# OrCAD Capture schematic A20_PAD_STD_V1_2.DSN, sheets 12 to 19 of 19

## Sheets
12 P12: NAND&eMMC: size A3; note: NAND&eMMC
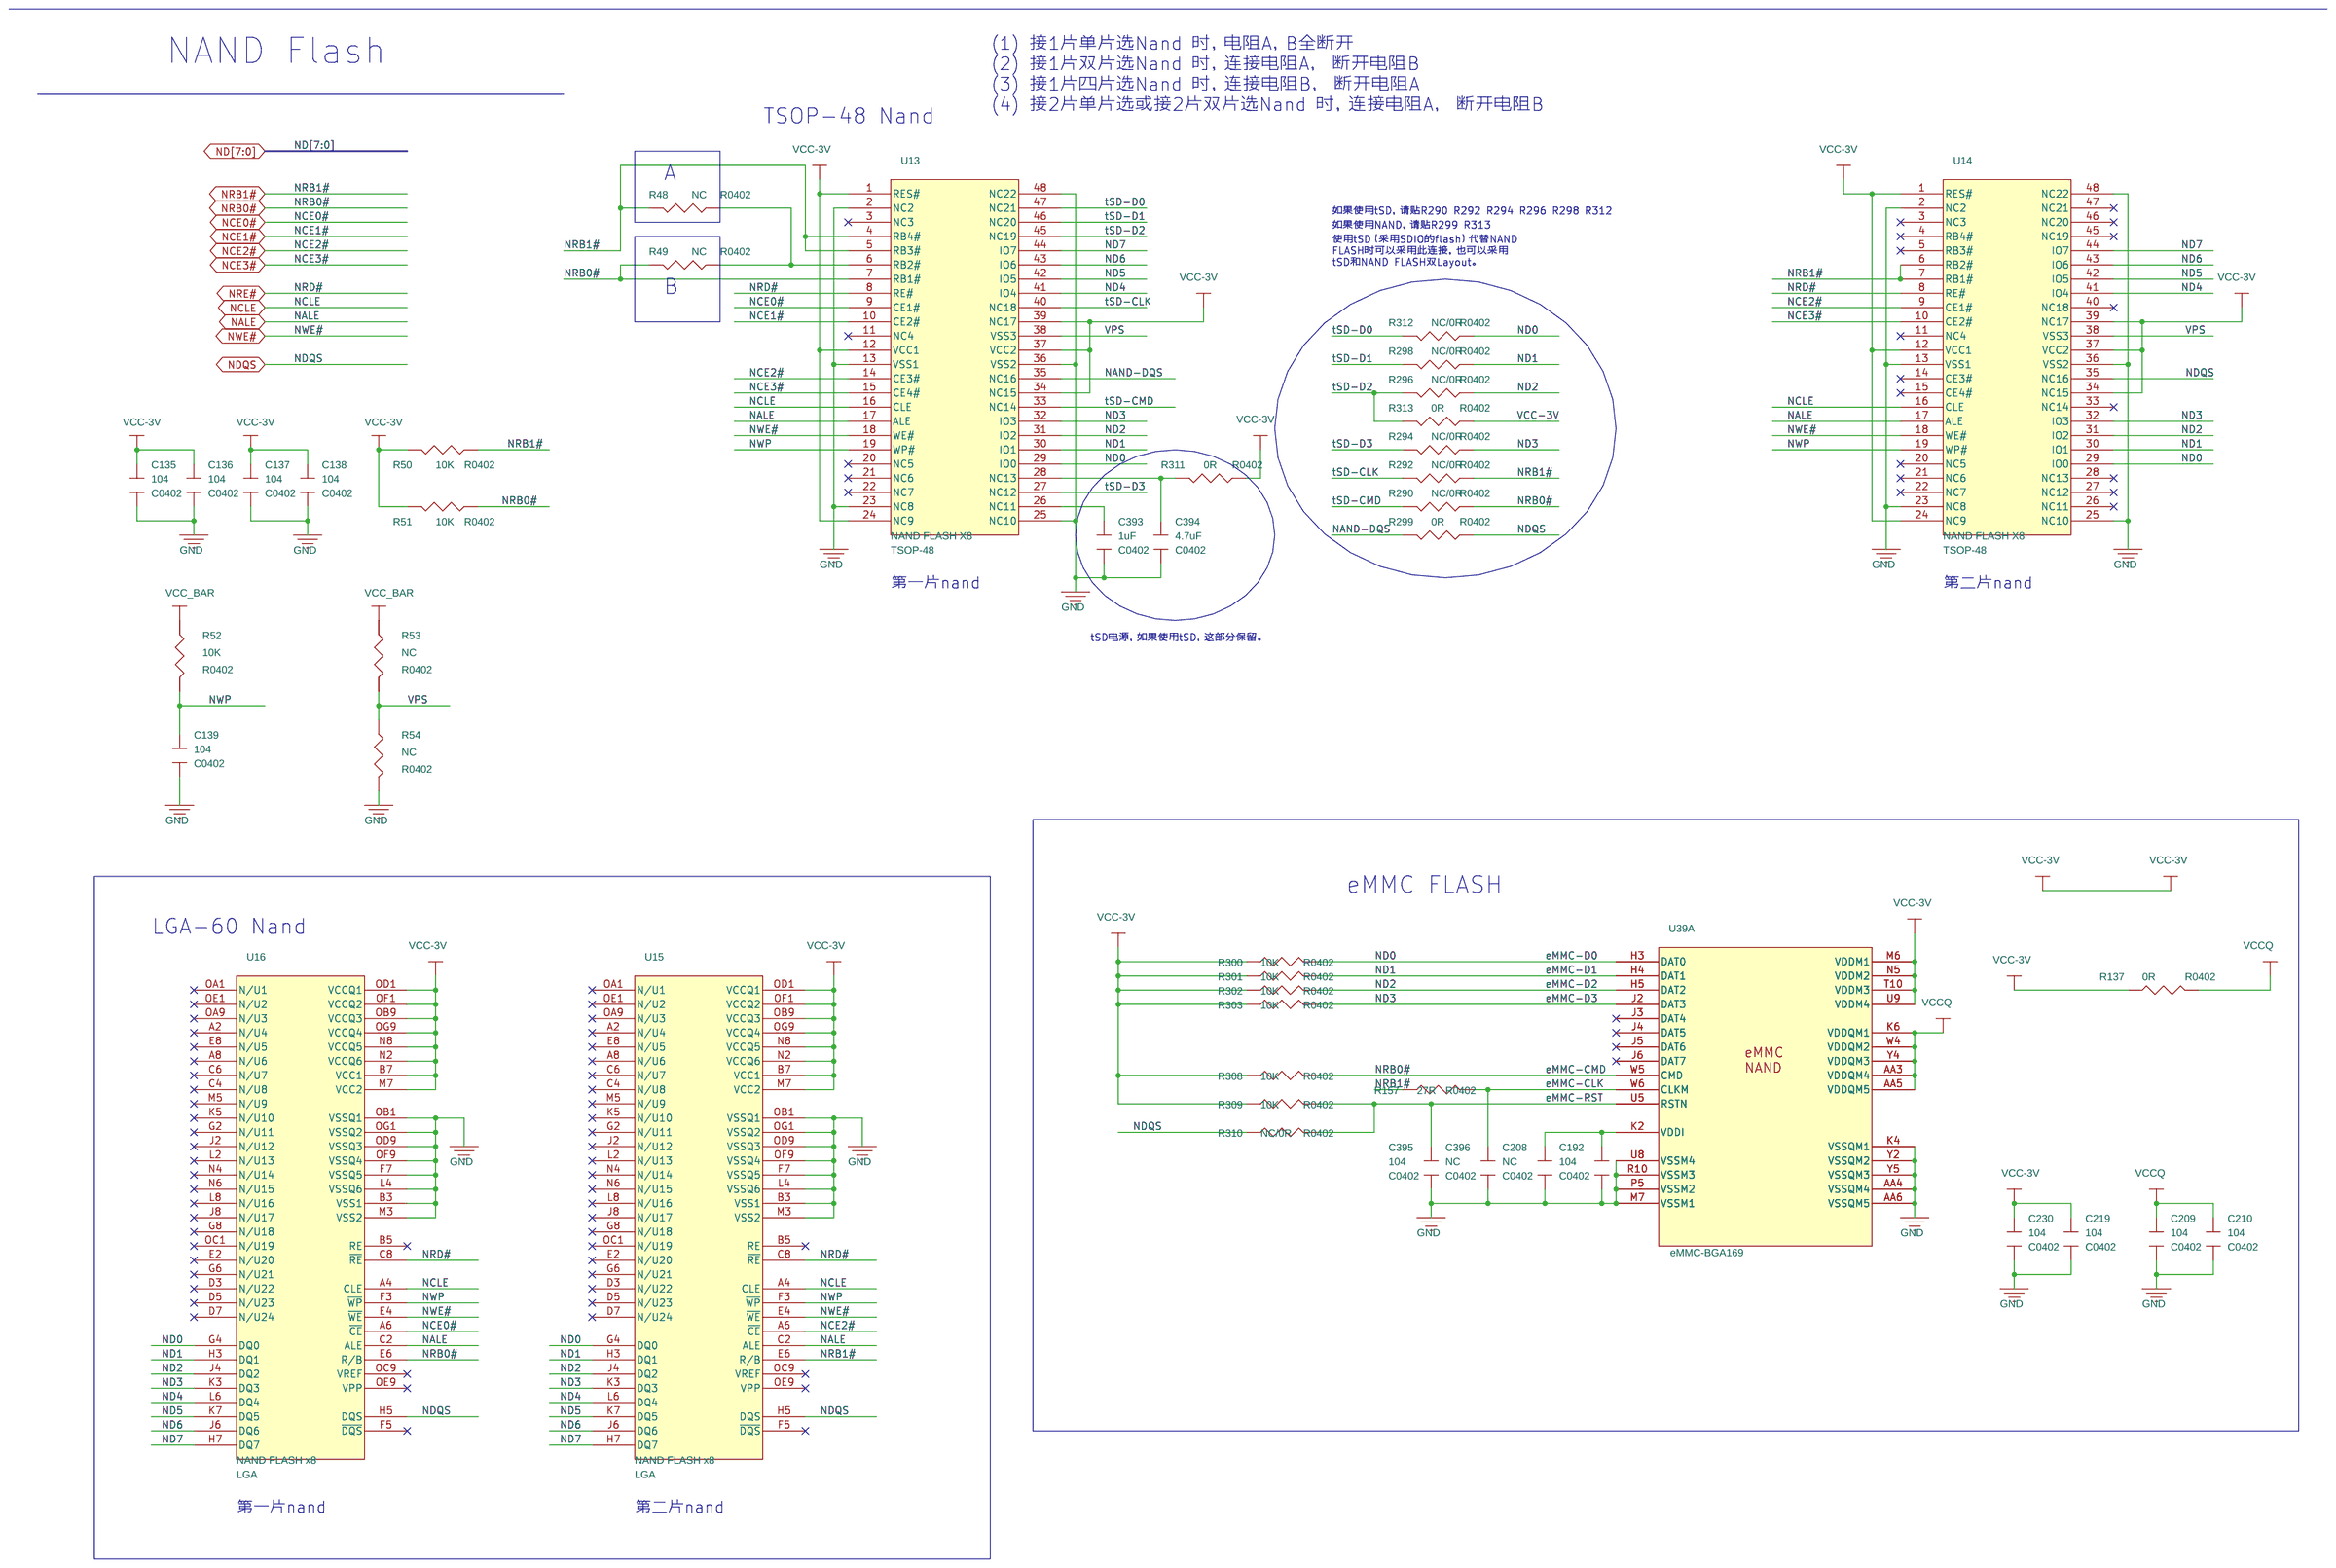
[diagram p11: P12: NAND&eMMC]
13 P15: CARD-DEBUG-GS: size A3; note: CARD-DEBUG-GS
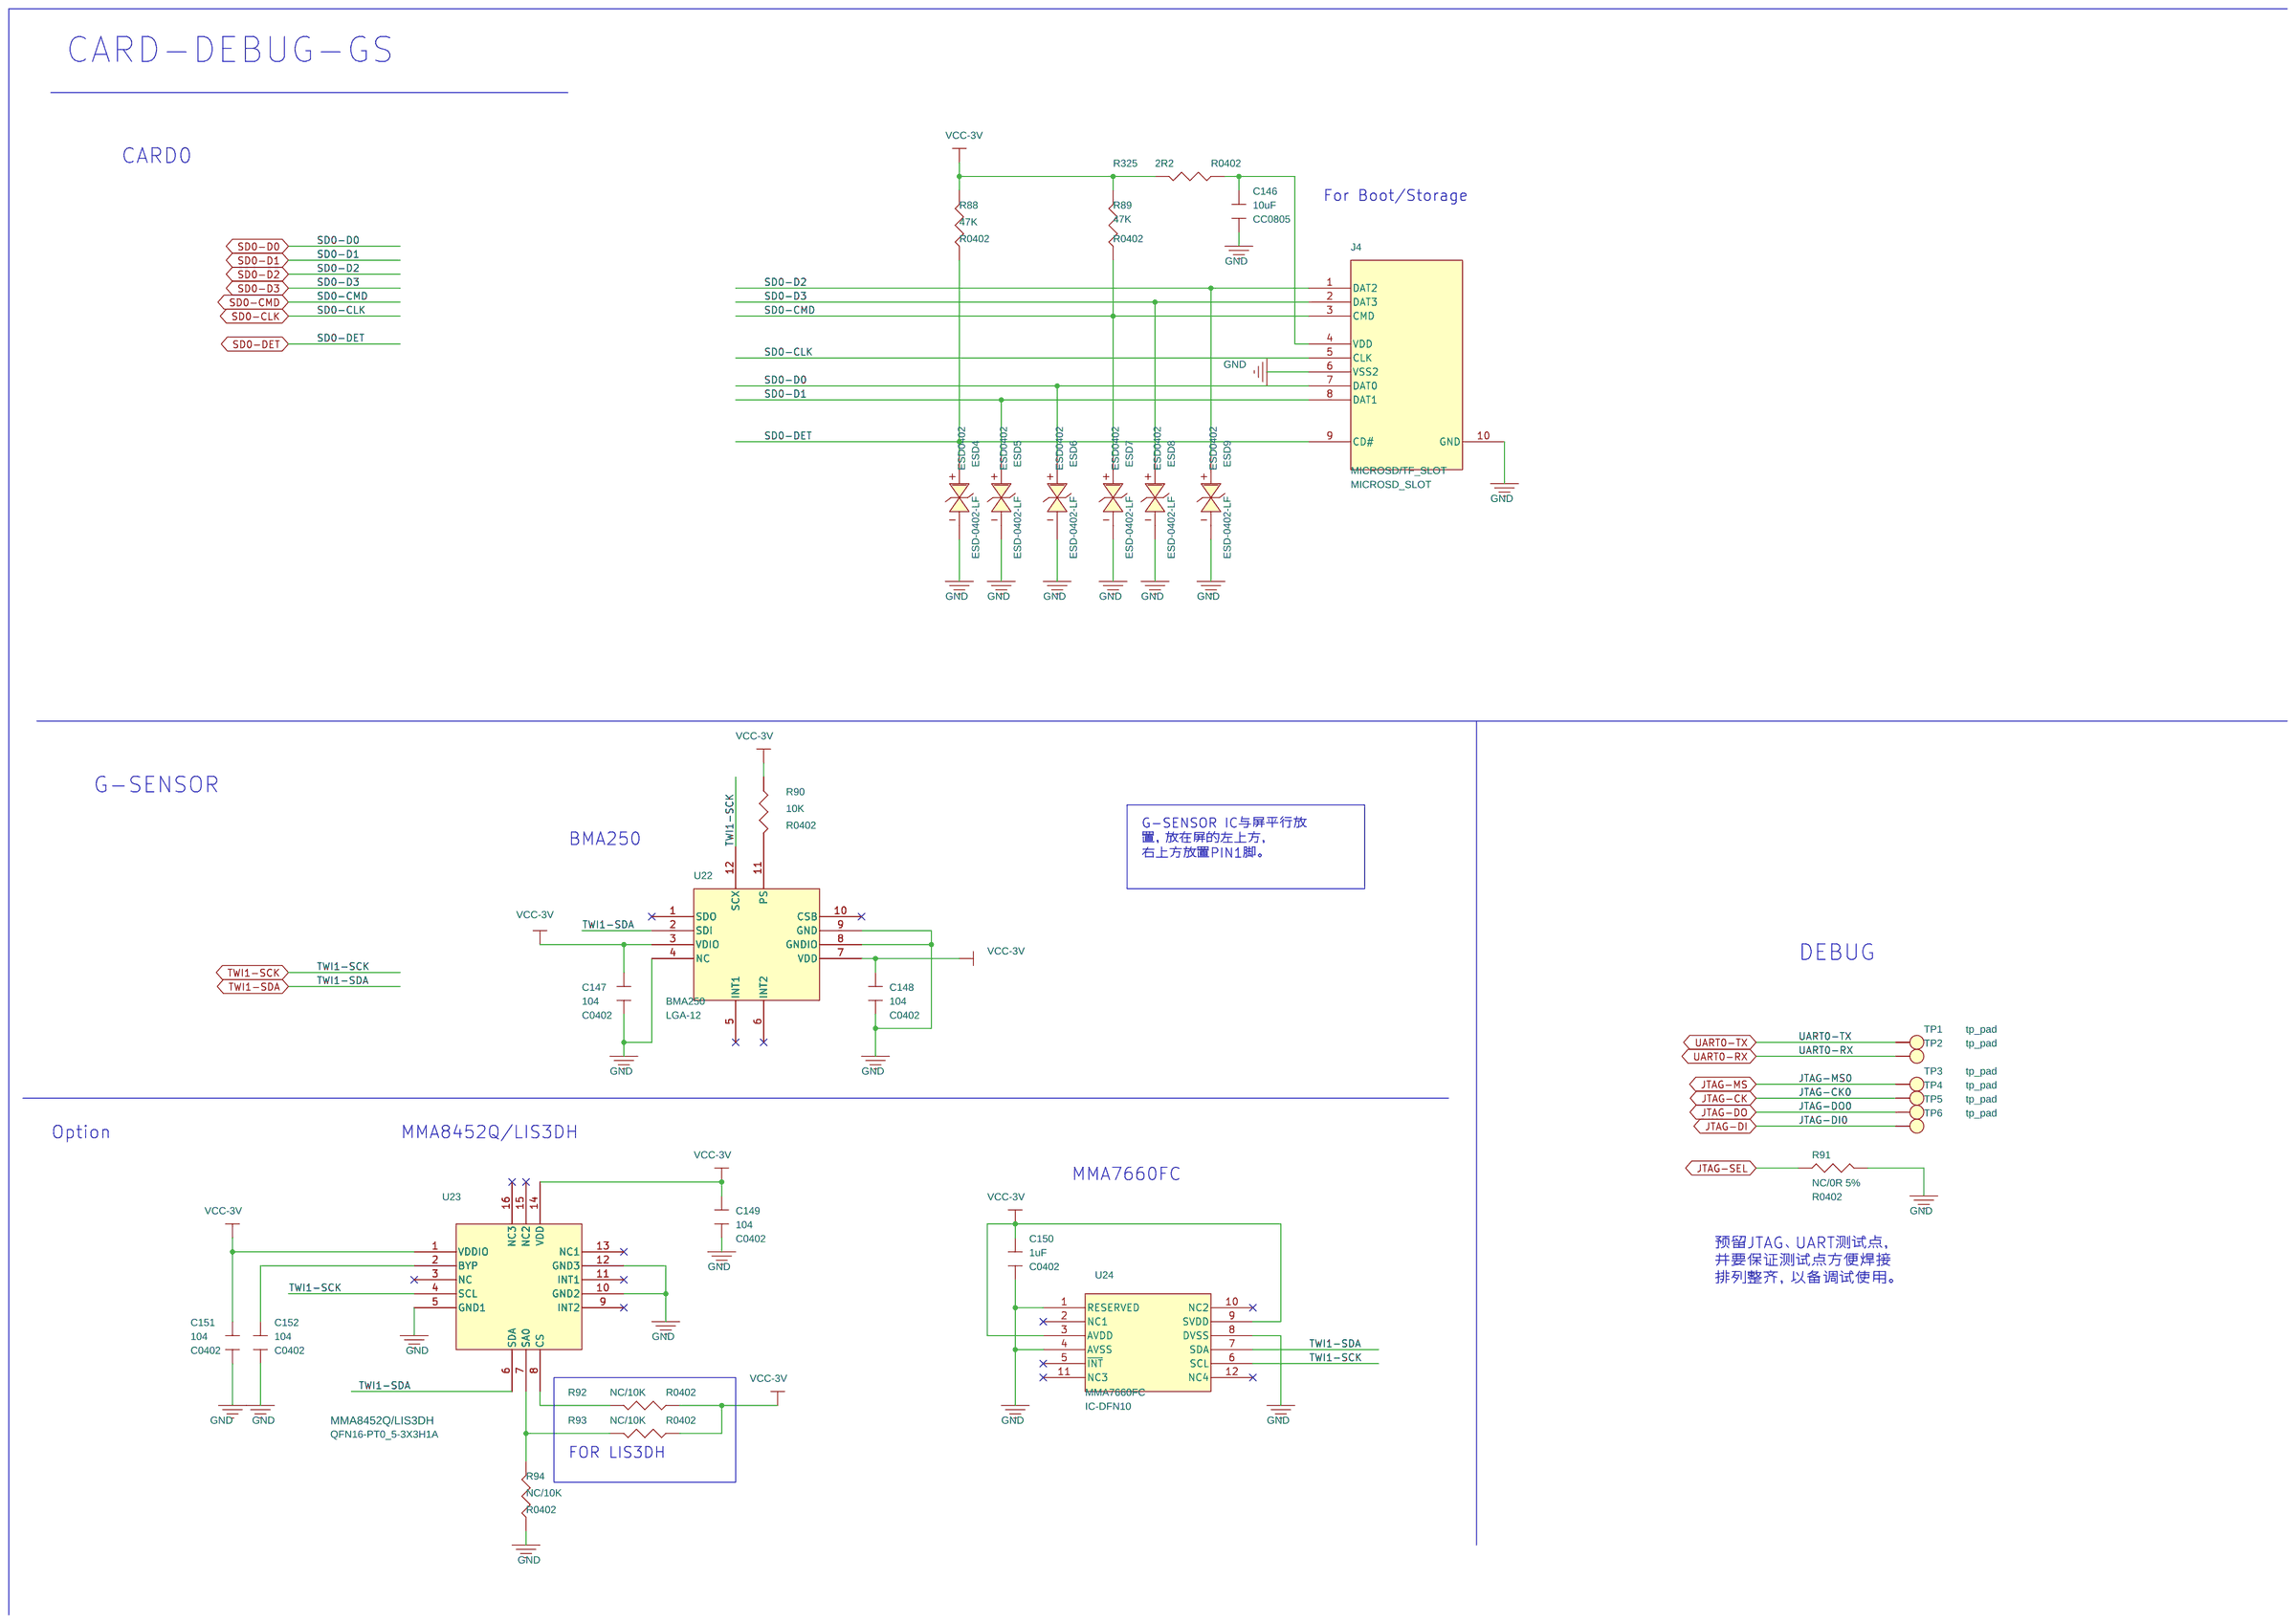
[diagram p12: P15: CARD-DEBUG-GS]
14 P09: BESIDE CPU: size A3; note: BESIDE CPU
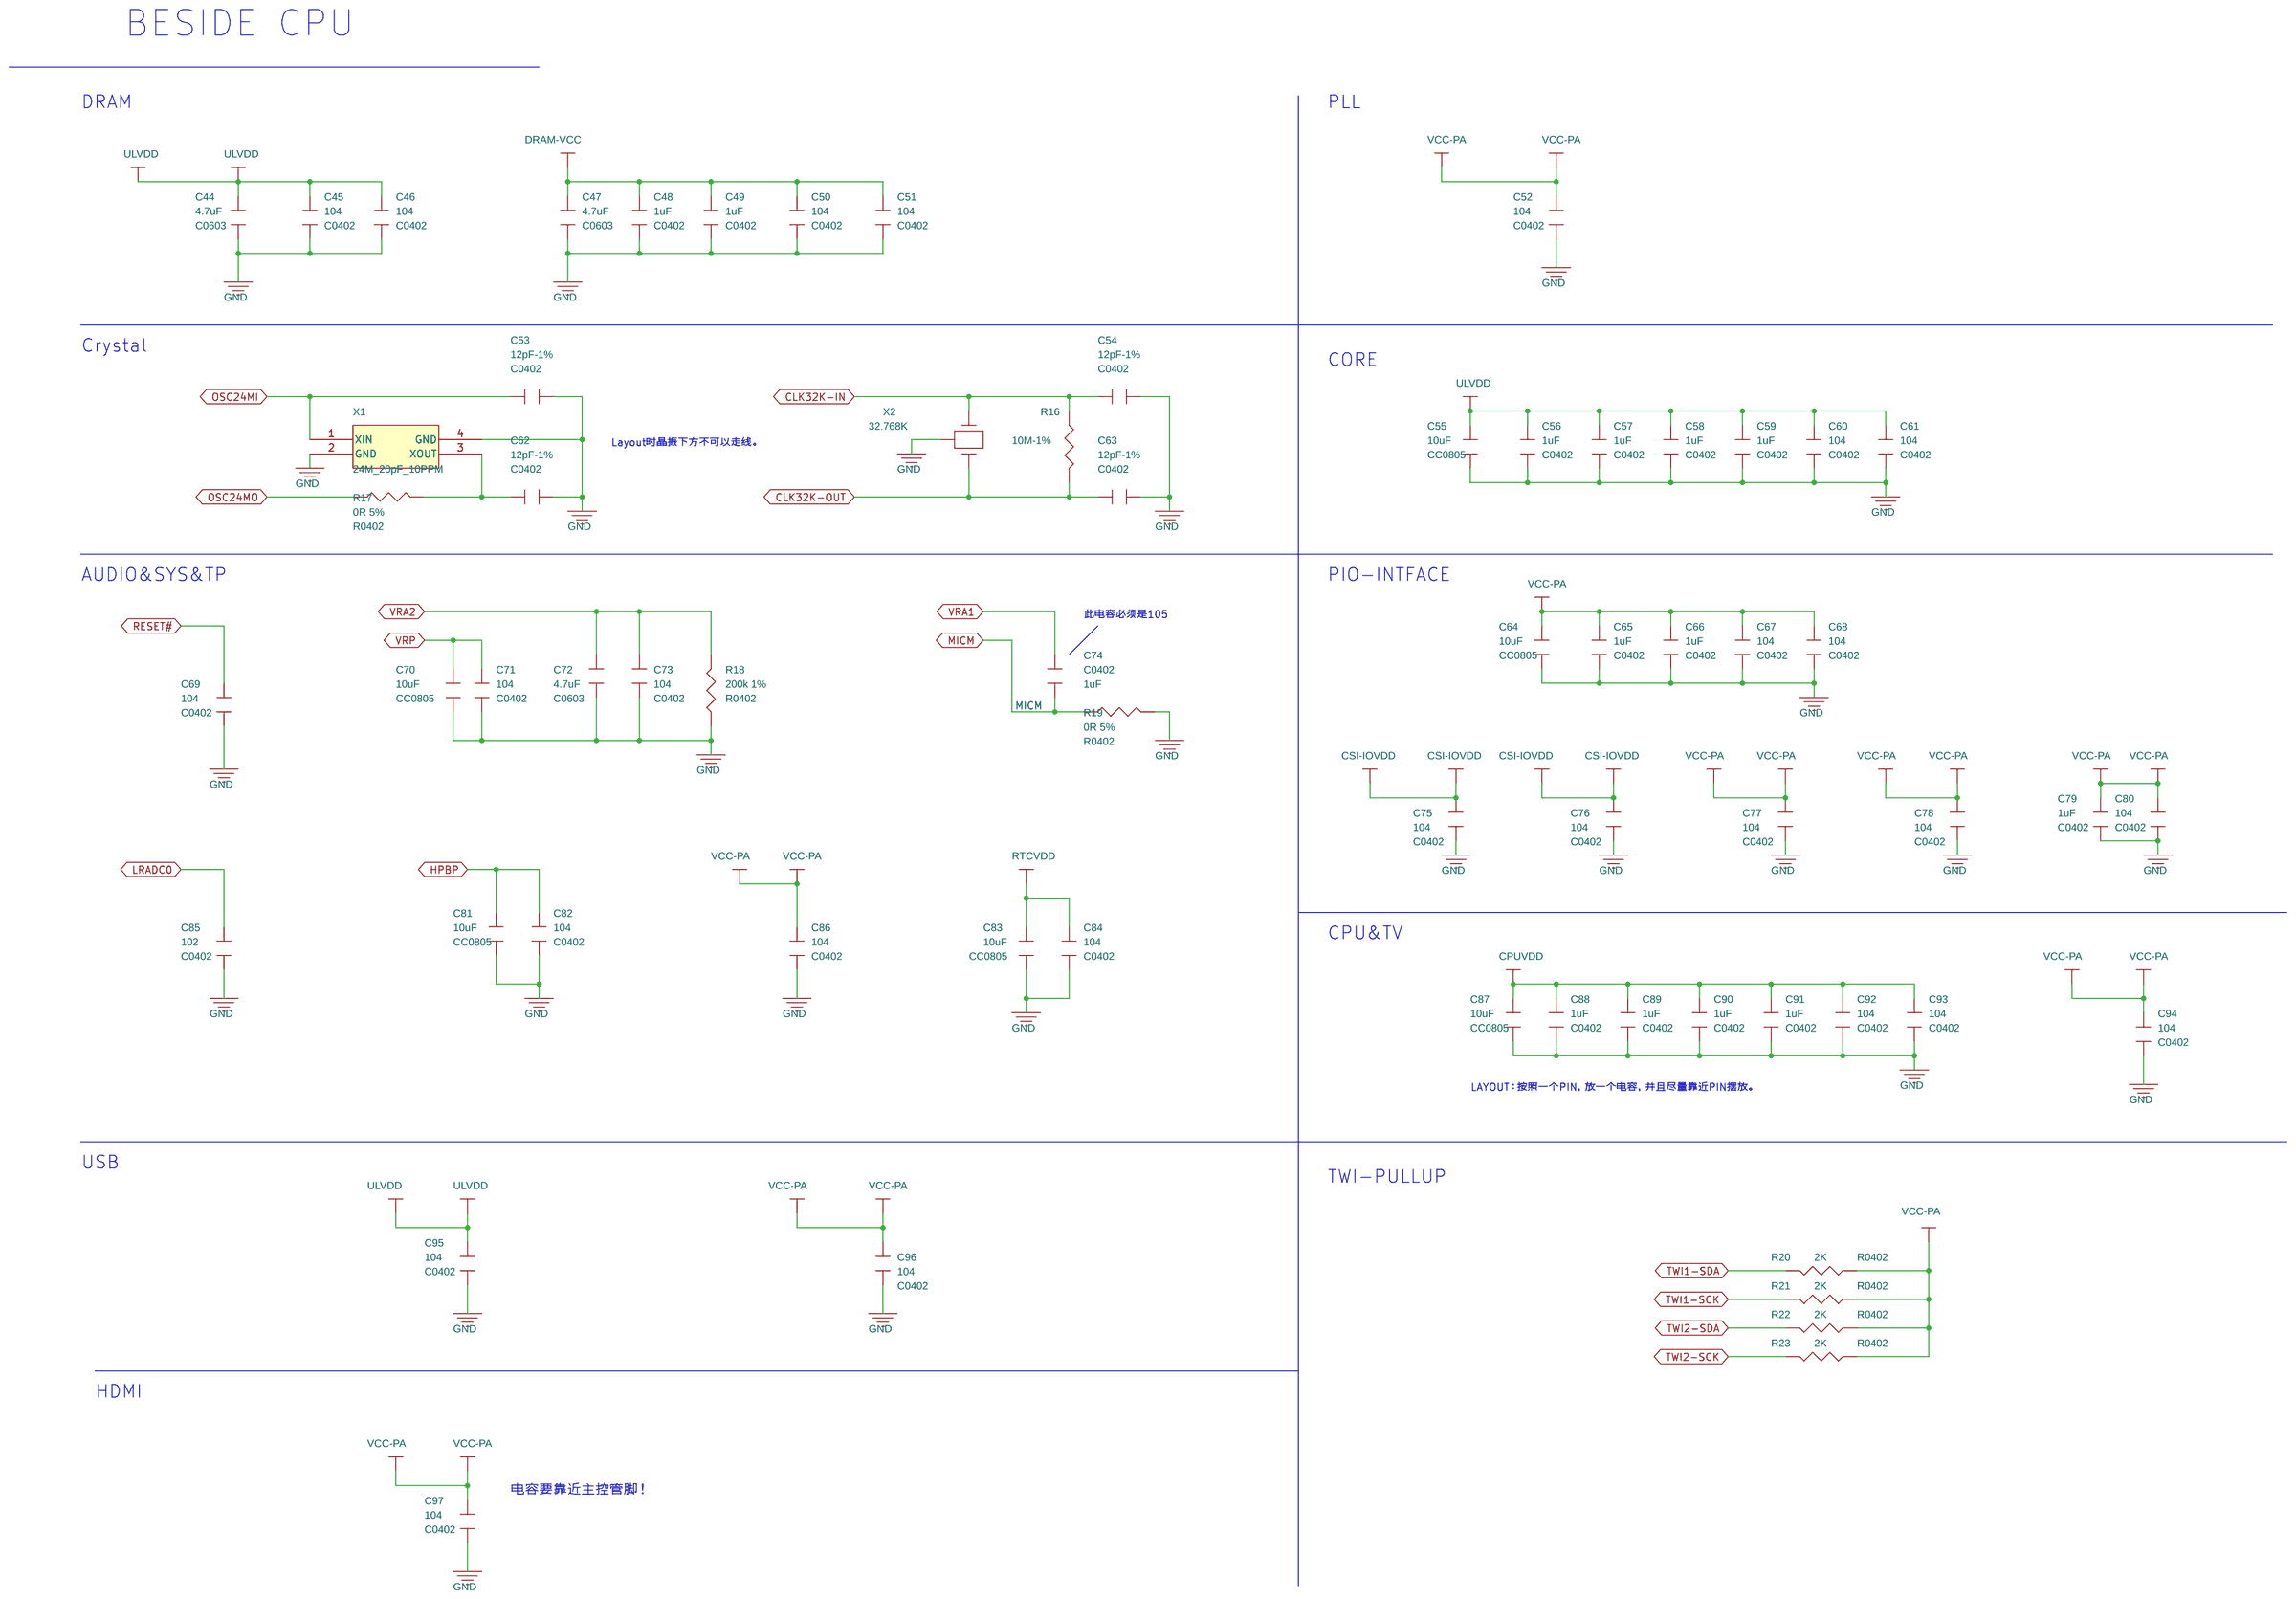
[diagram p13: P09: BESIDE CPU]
15 P19: HP-MIC-SPK: size A3; note: HP-MIC-SPK
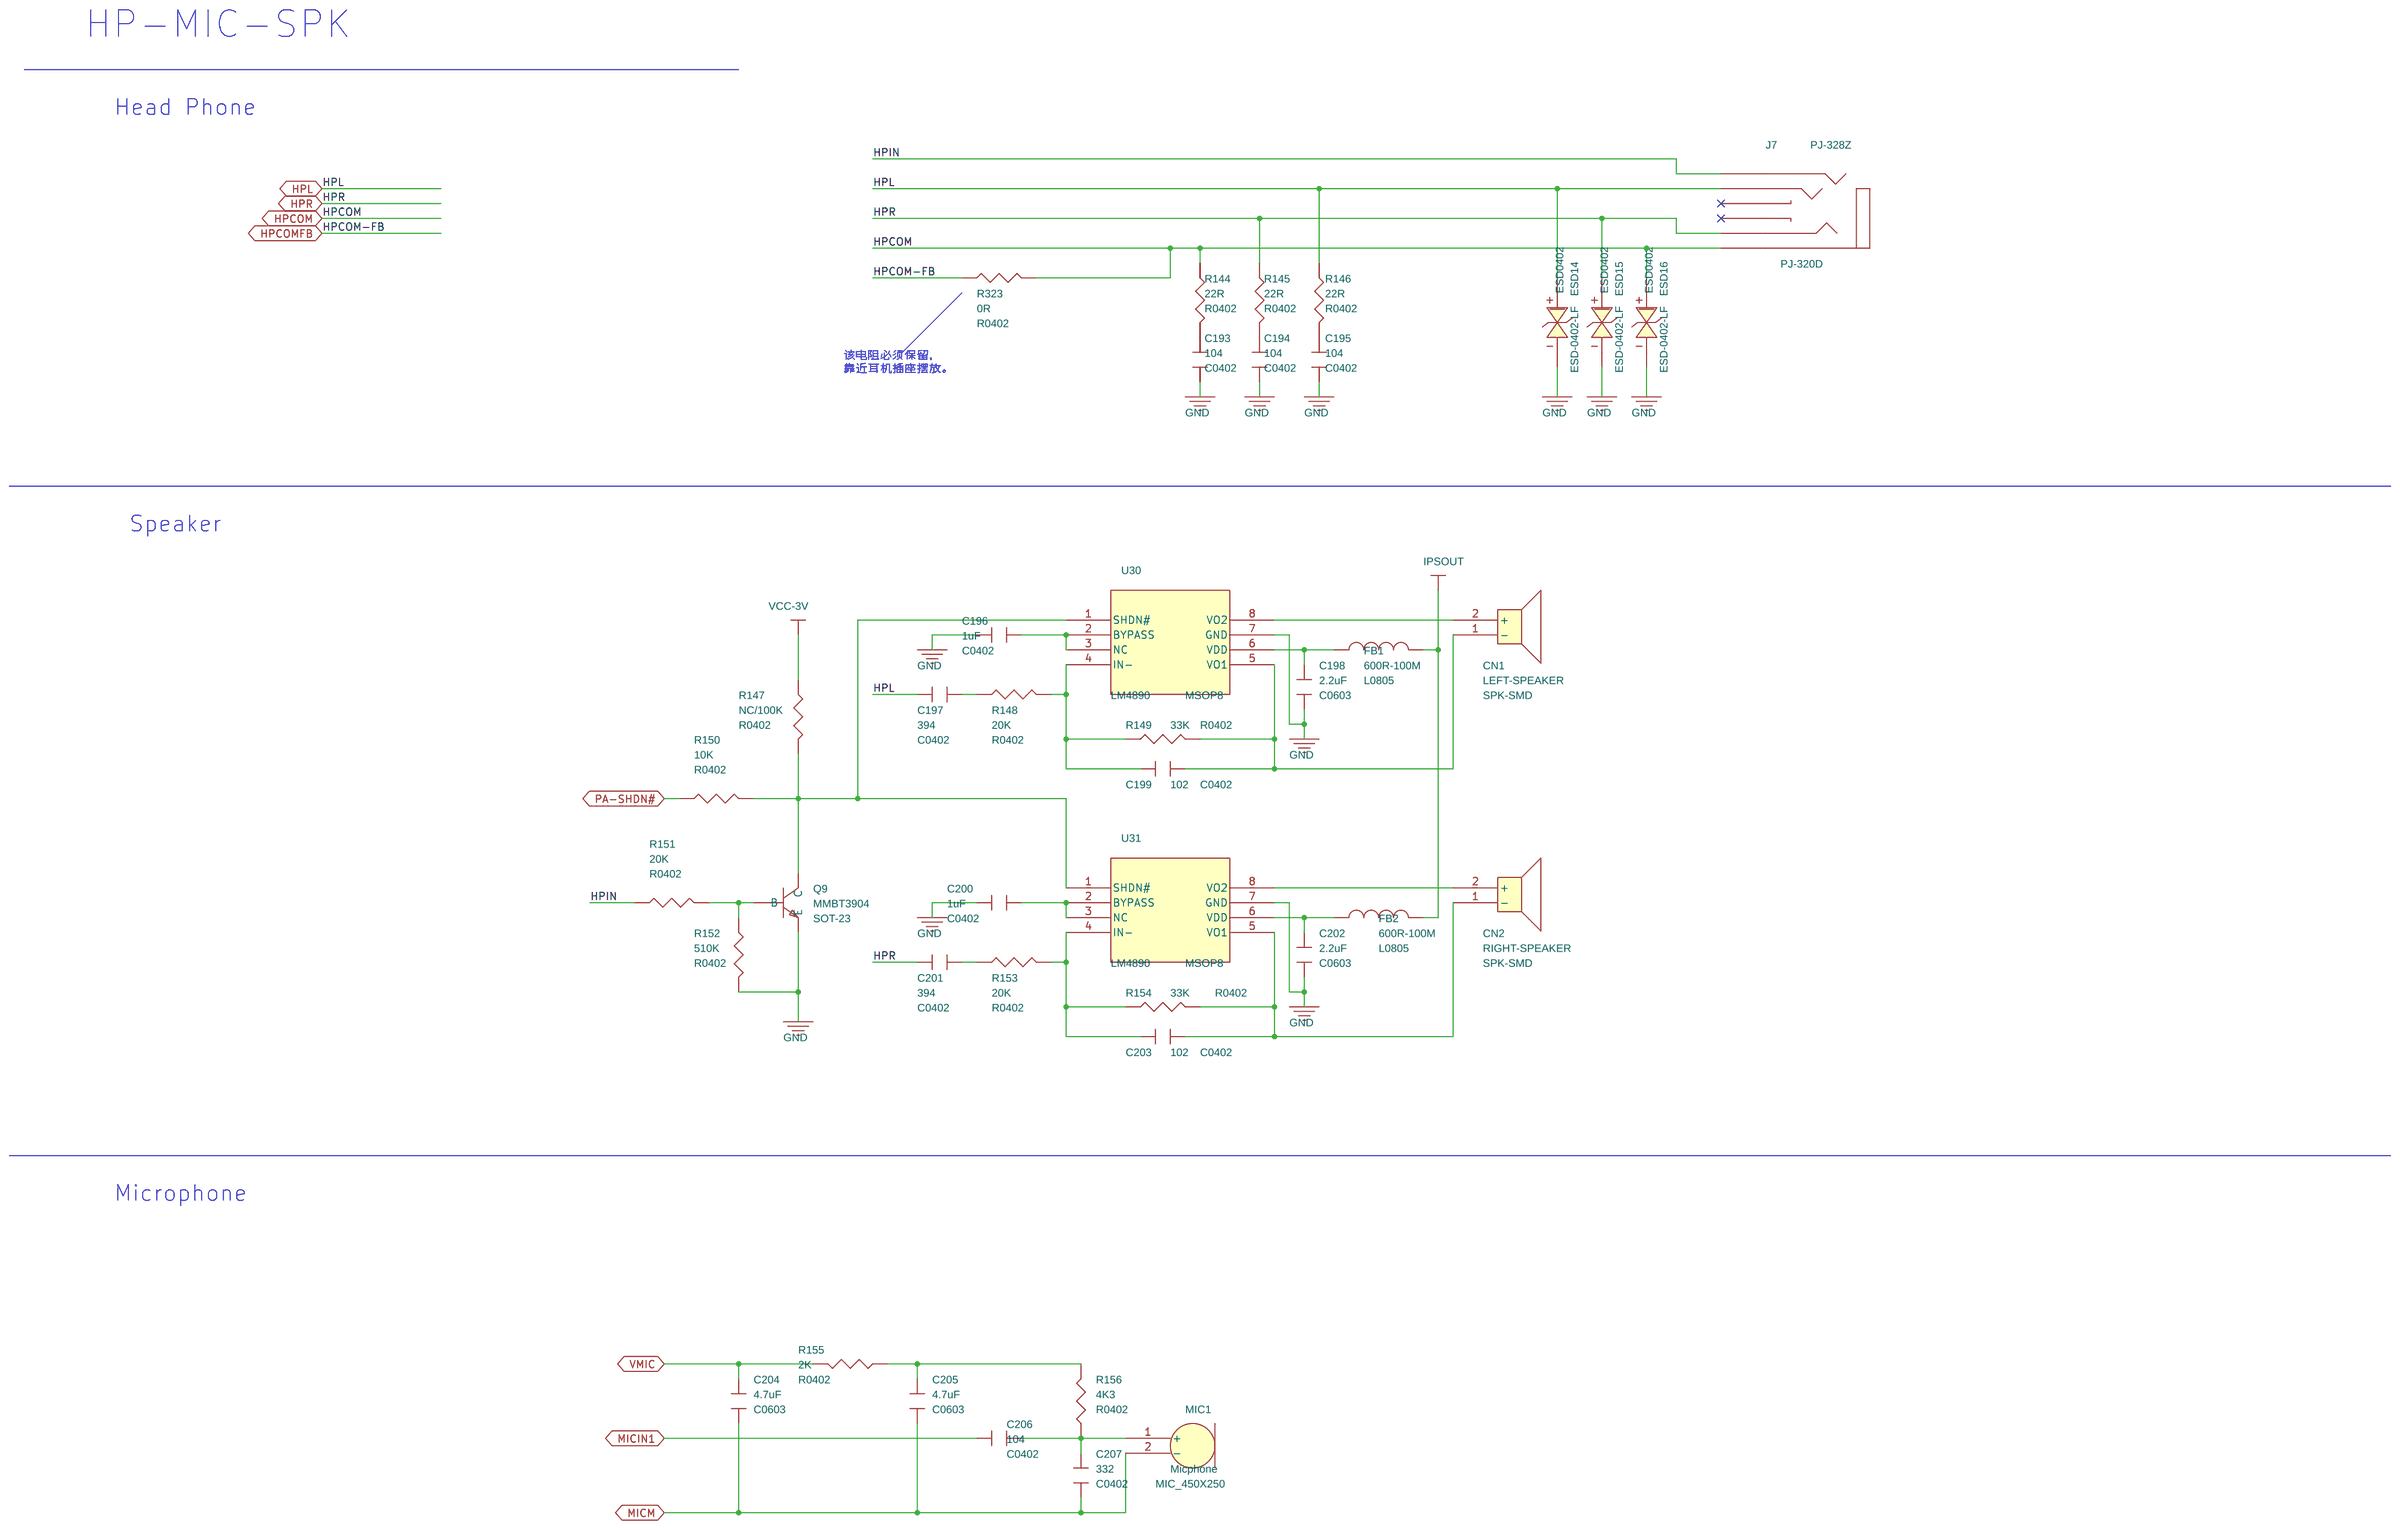
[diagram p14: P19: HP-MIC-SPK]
16 P03: PIO ASSIGNMENT: note: PIO ASSIGNMENT
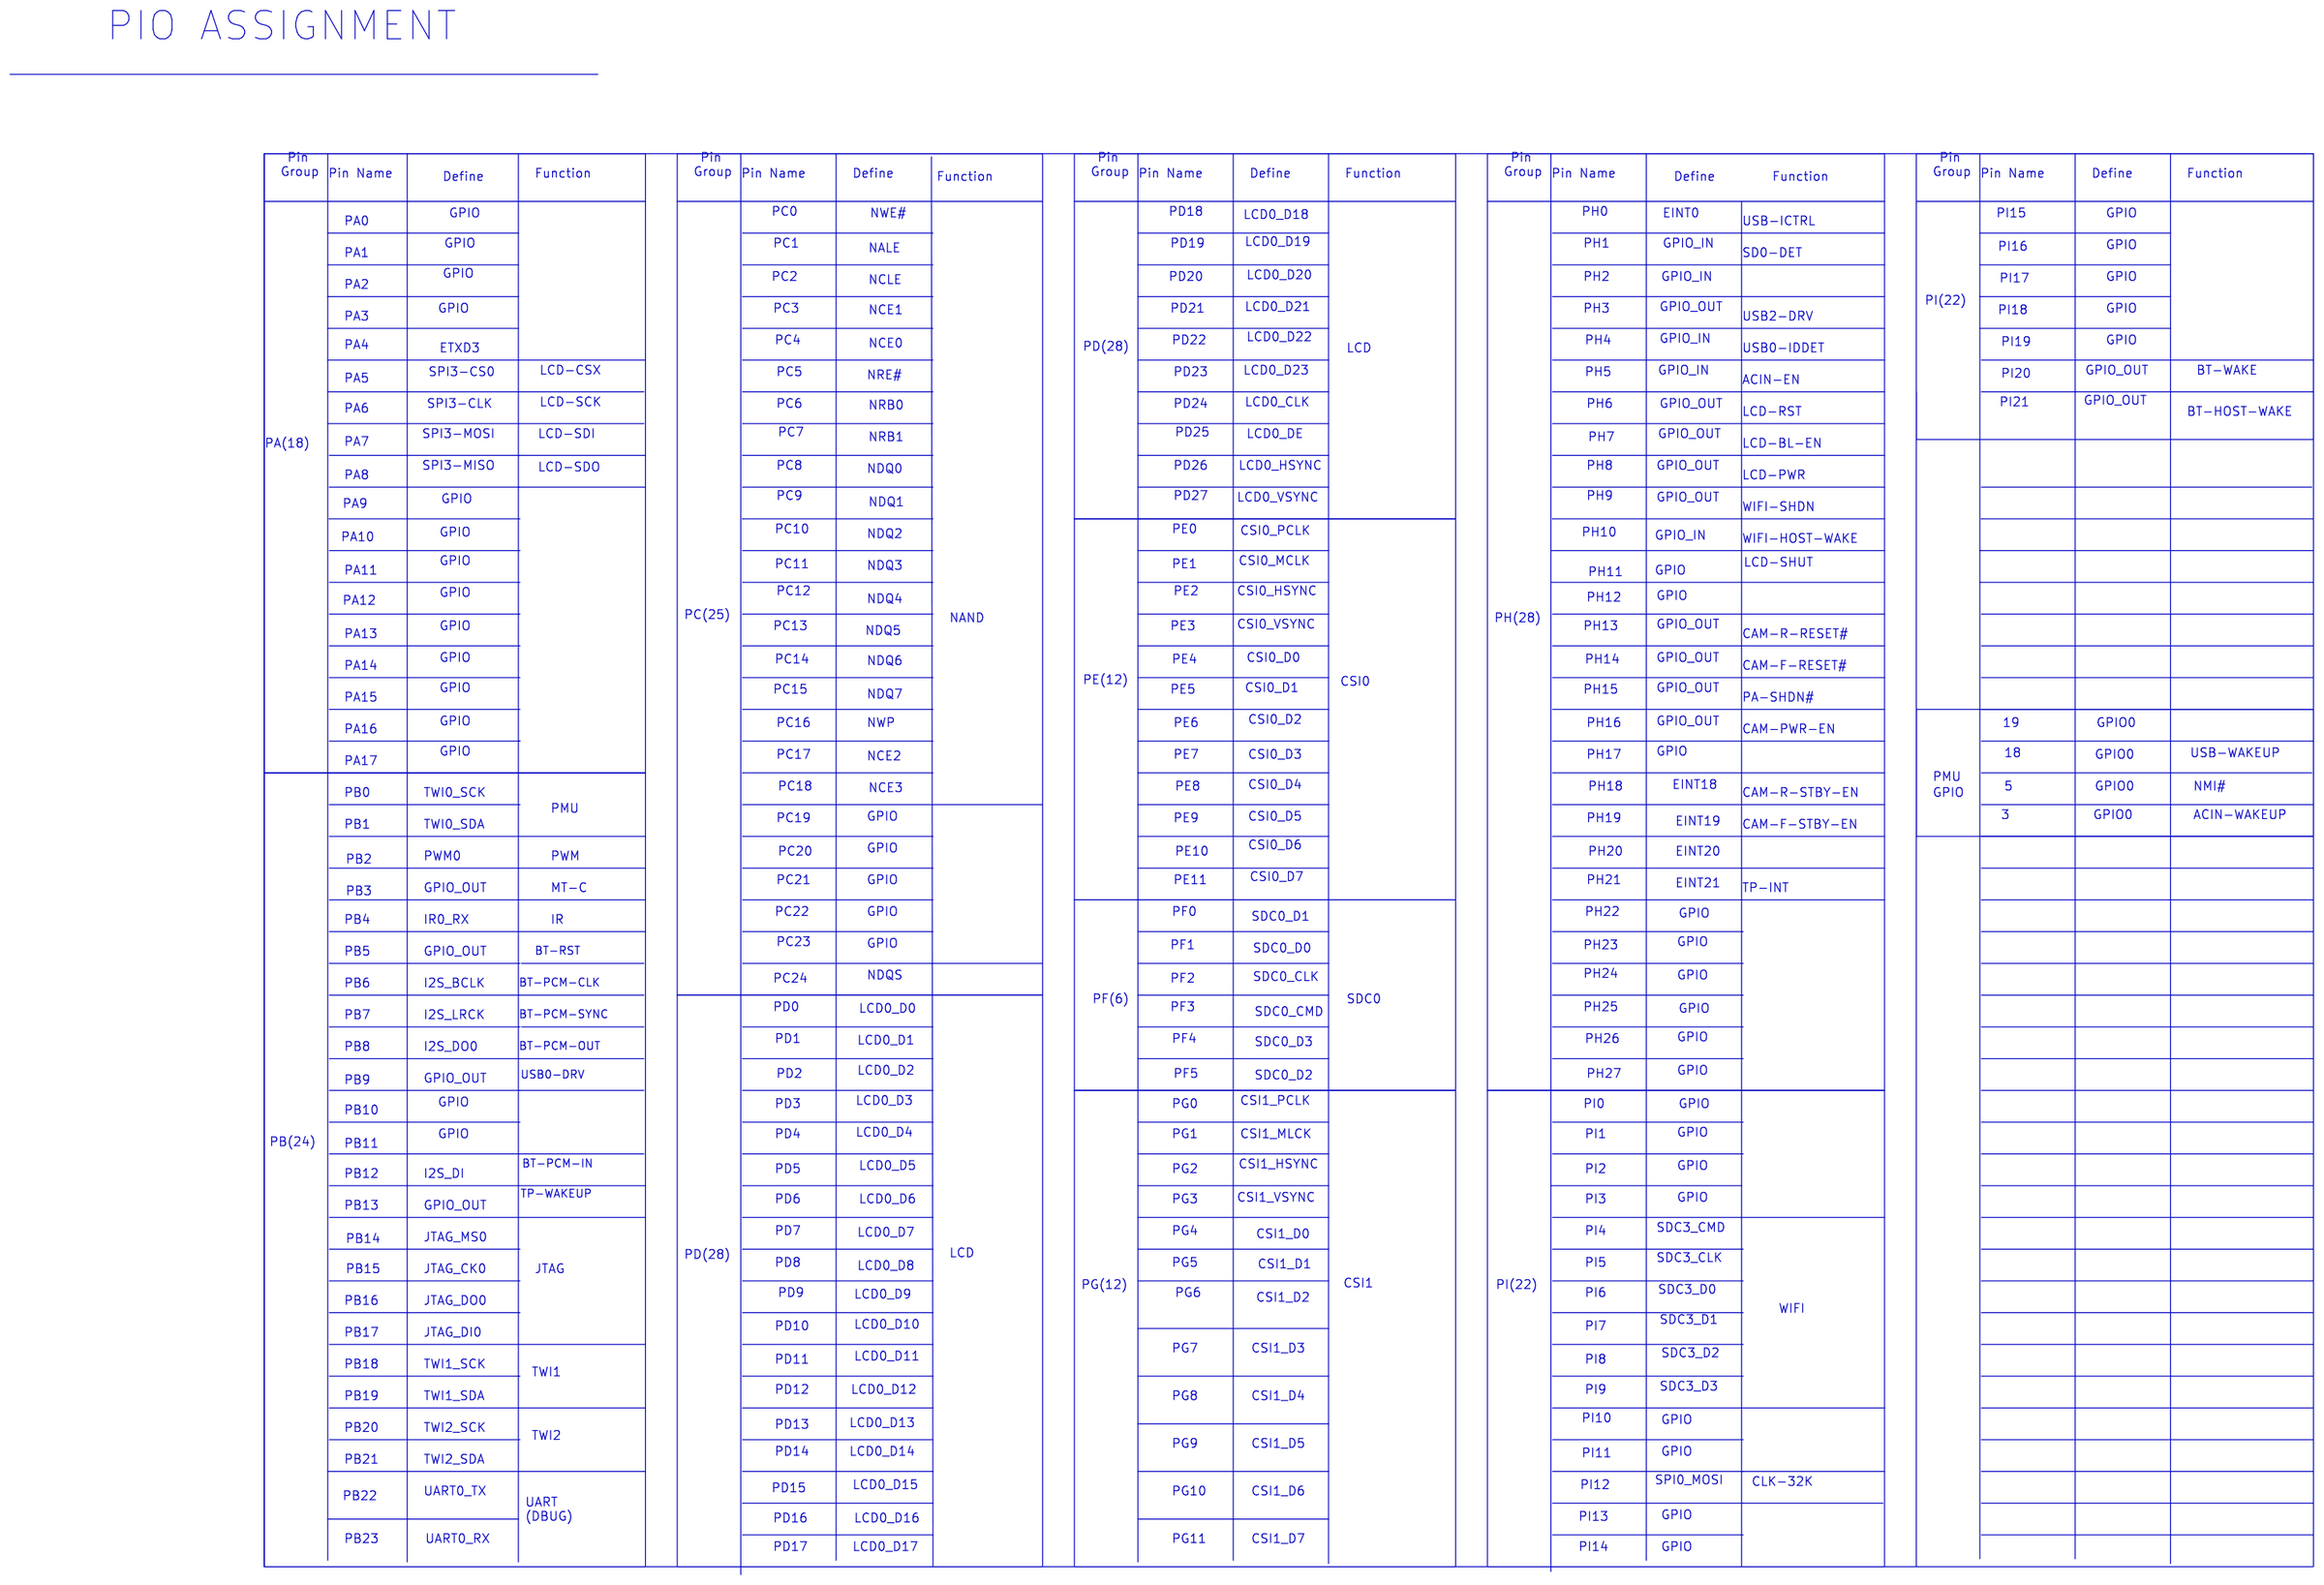
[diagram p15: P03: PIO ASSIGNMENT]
17 P07: DDR3 8bit x 4pcs: size A3; note: DDR3 8bit*4pcs
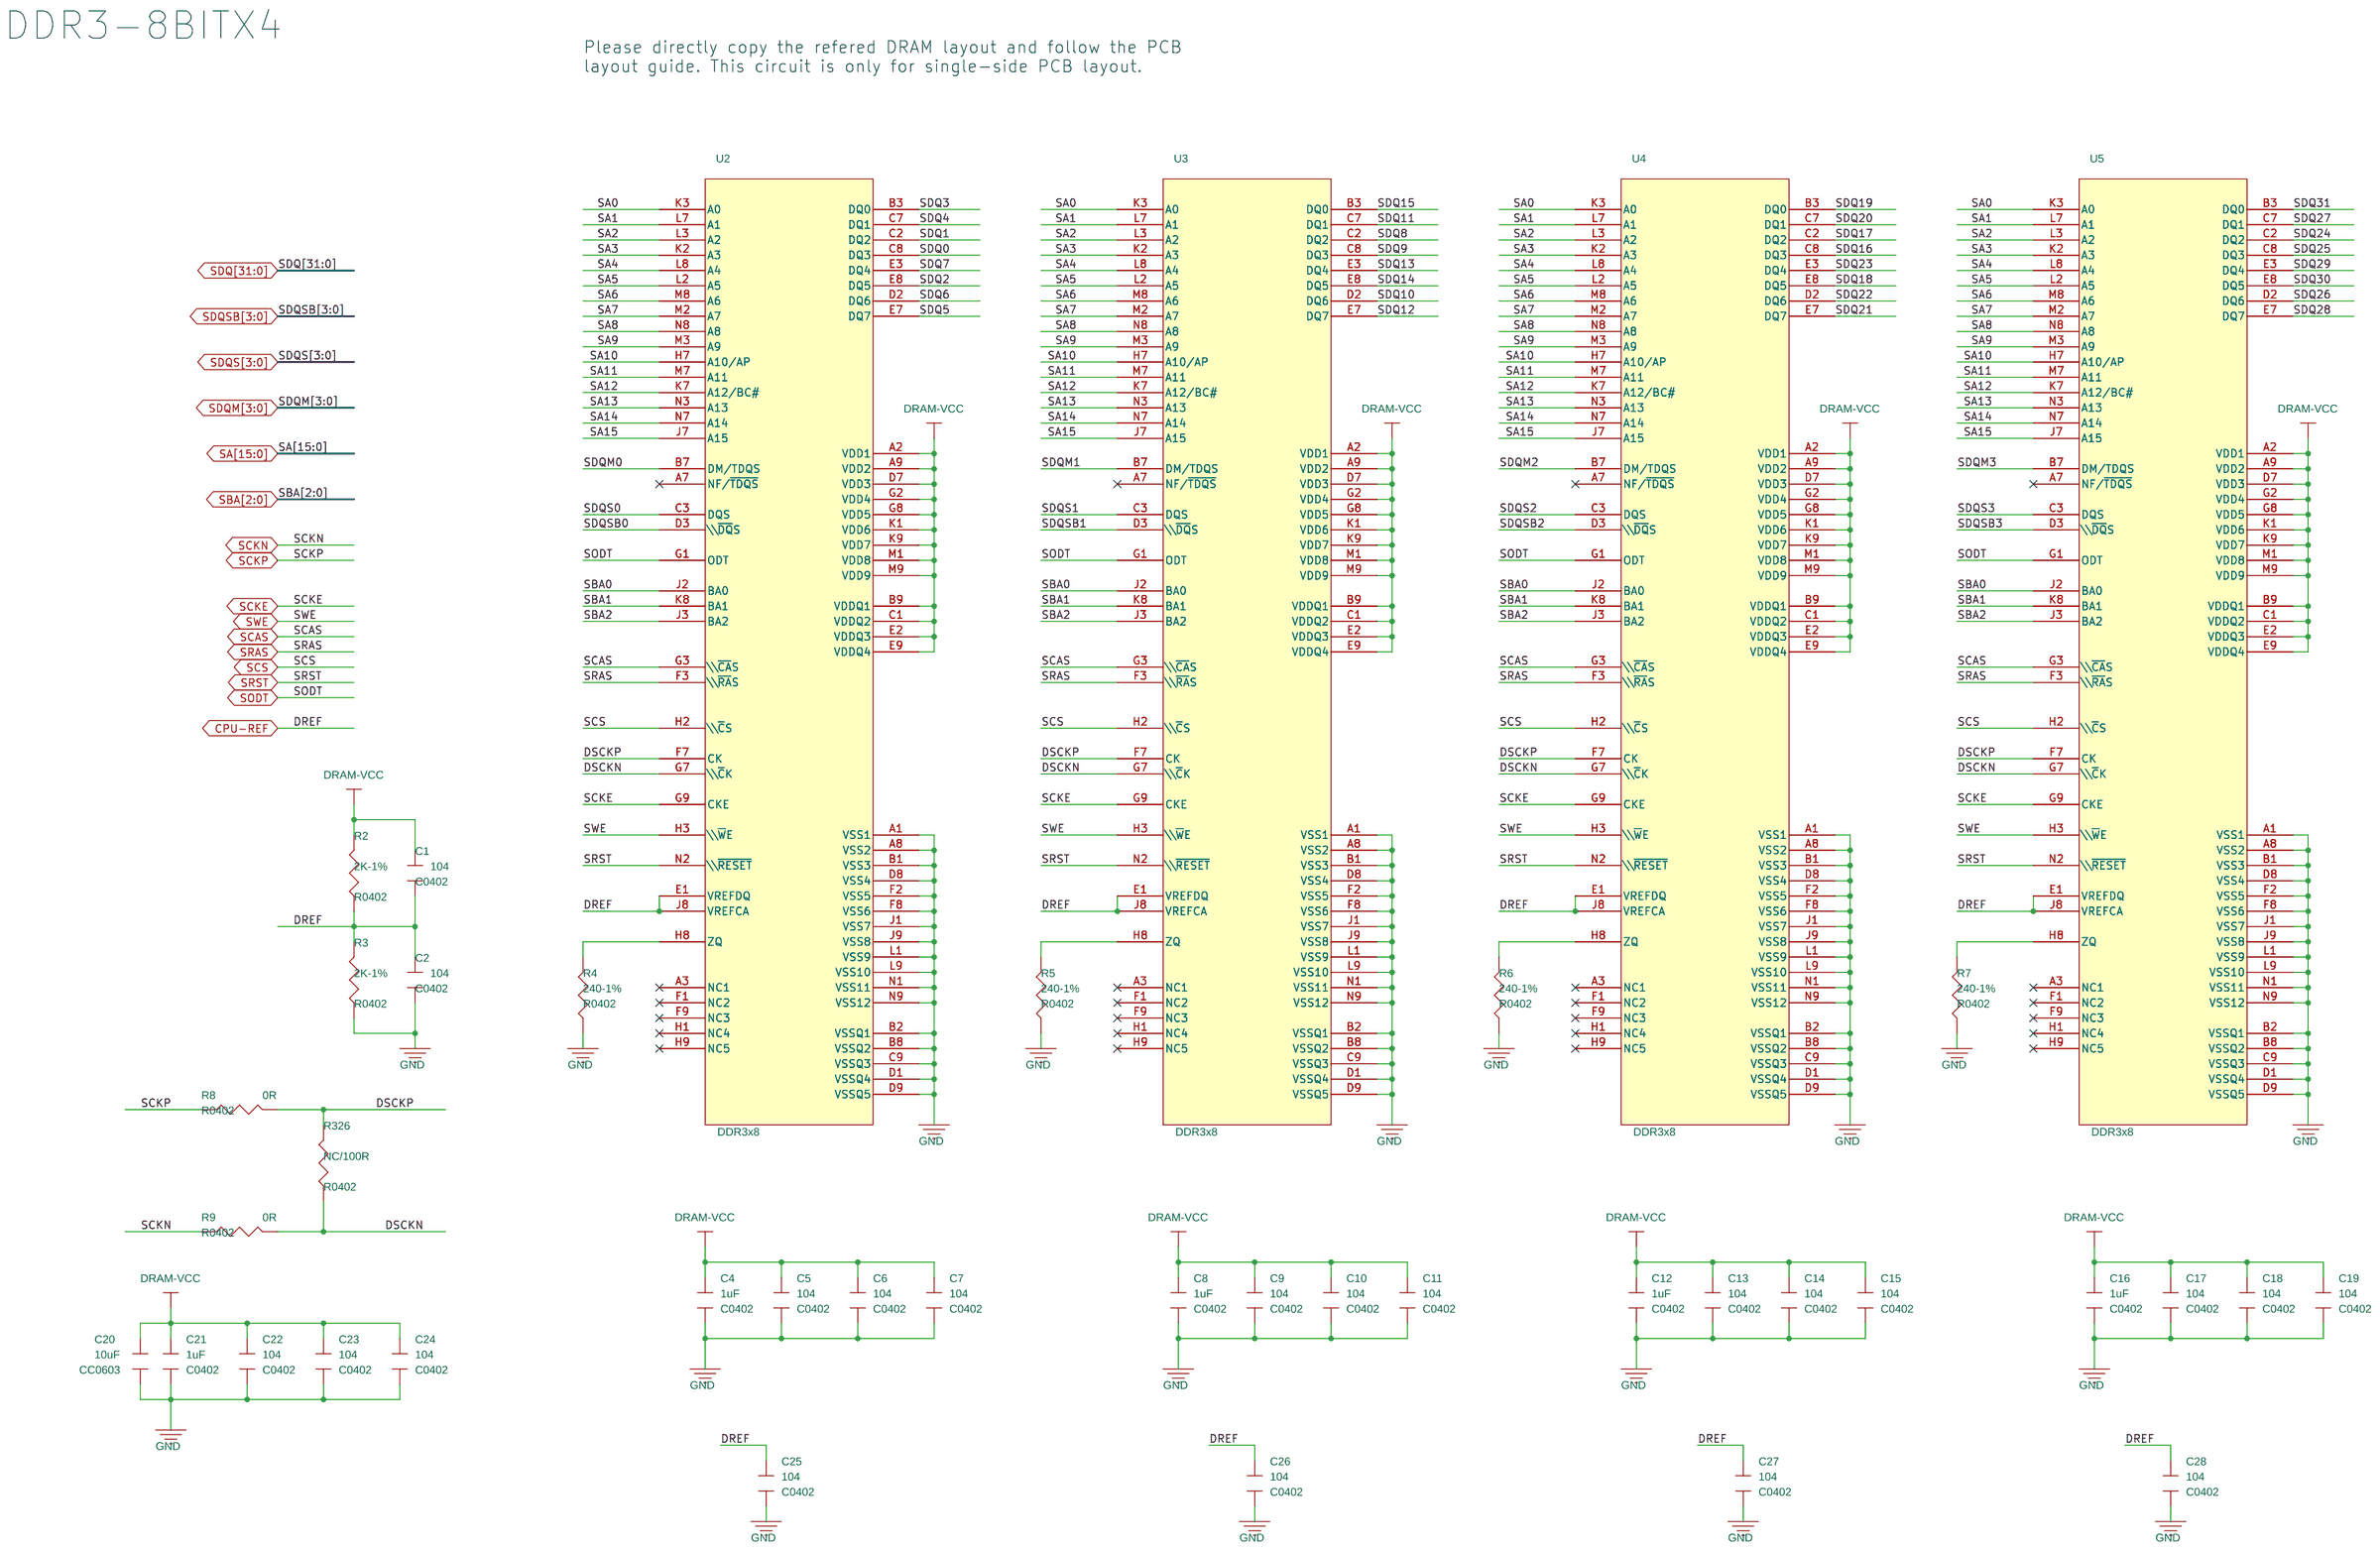
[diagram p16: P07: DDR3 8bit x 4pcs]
18 P14: KEY-IR-TVOUT-MT: size A3; note: KEY-IR-TVOUT-MT
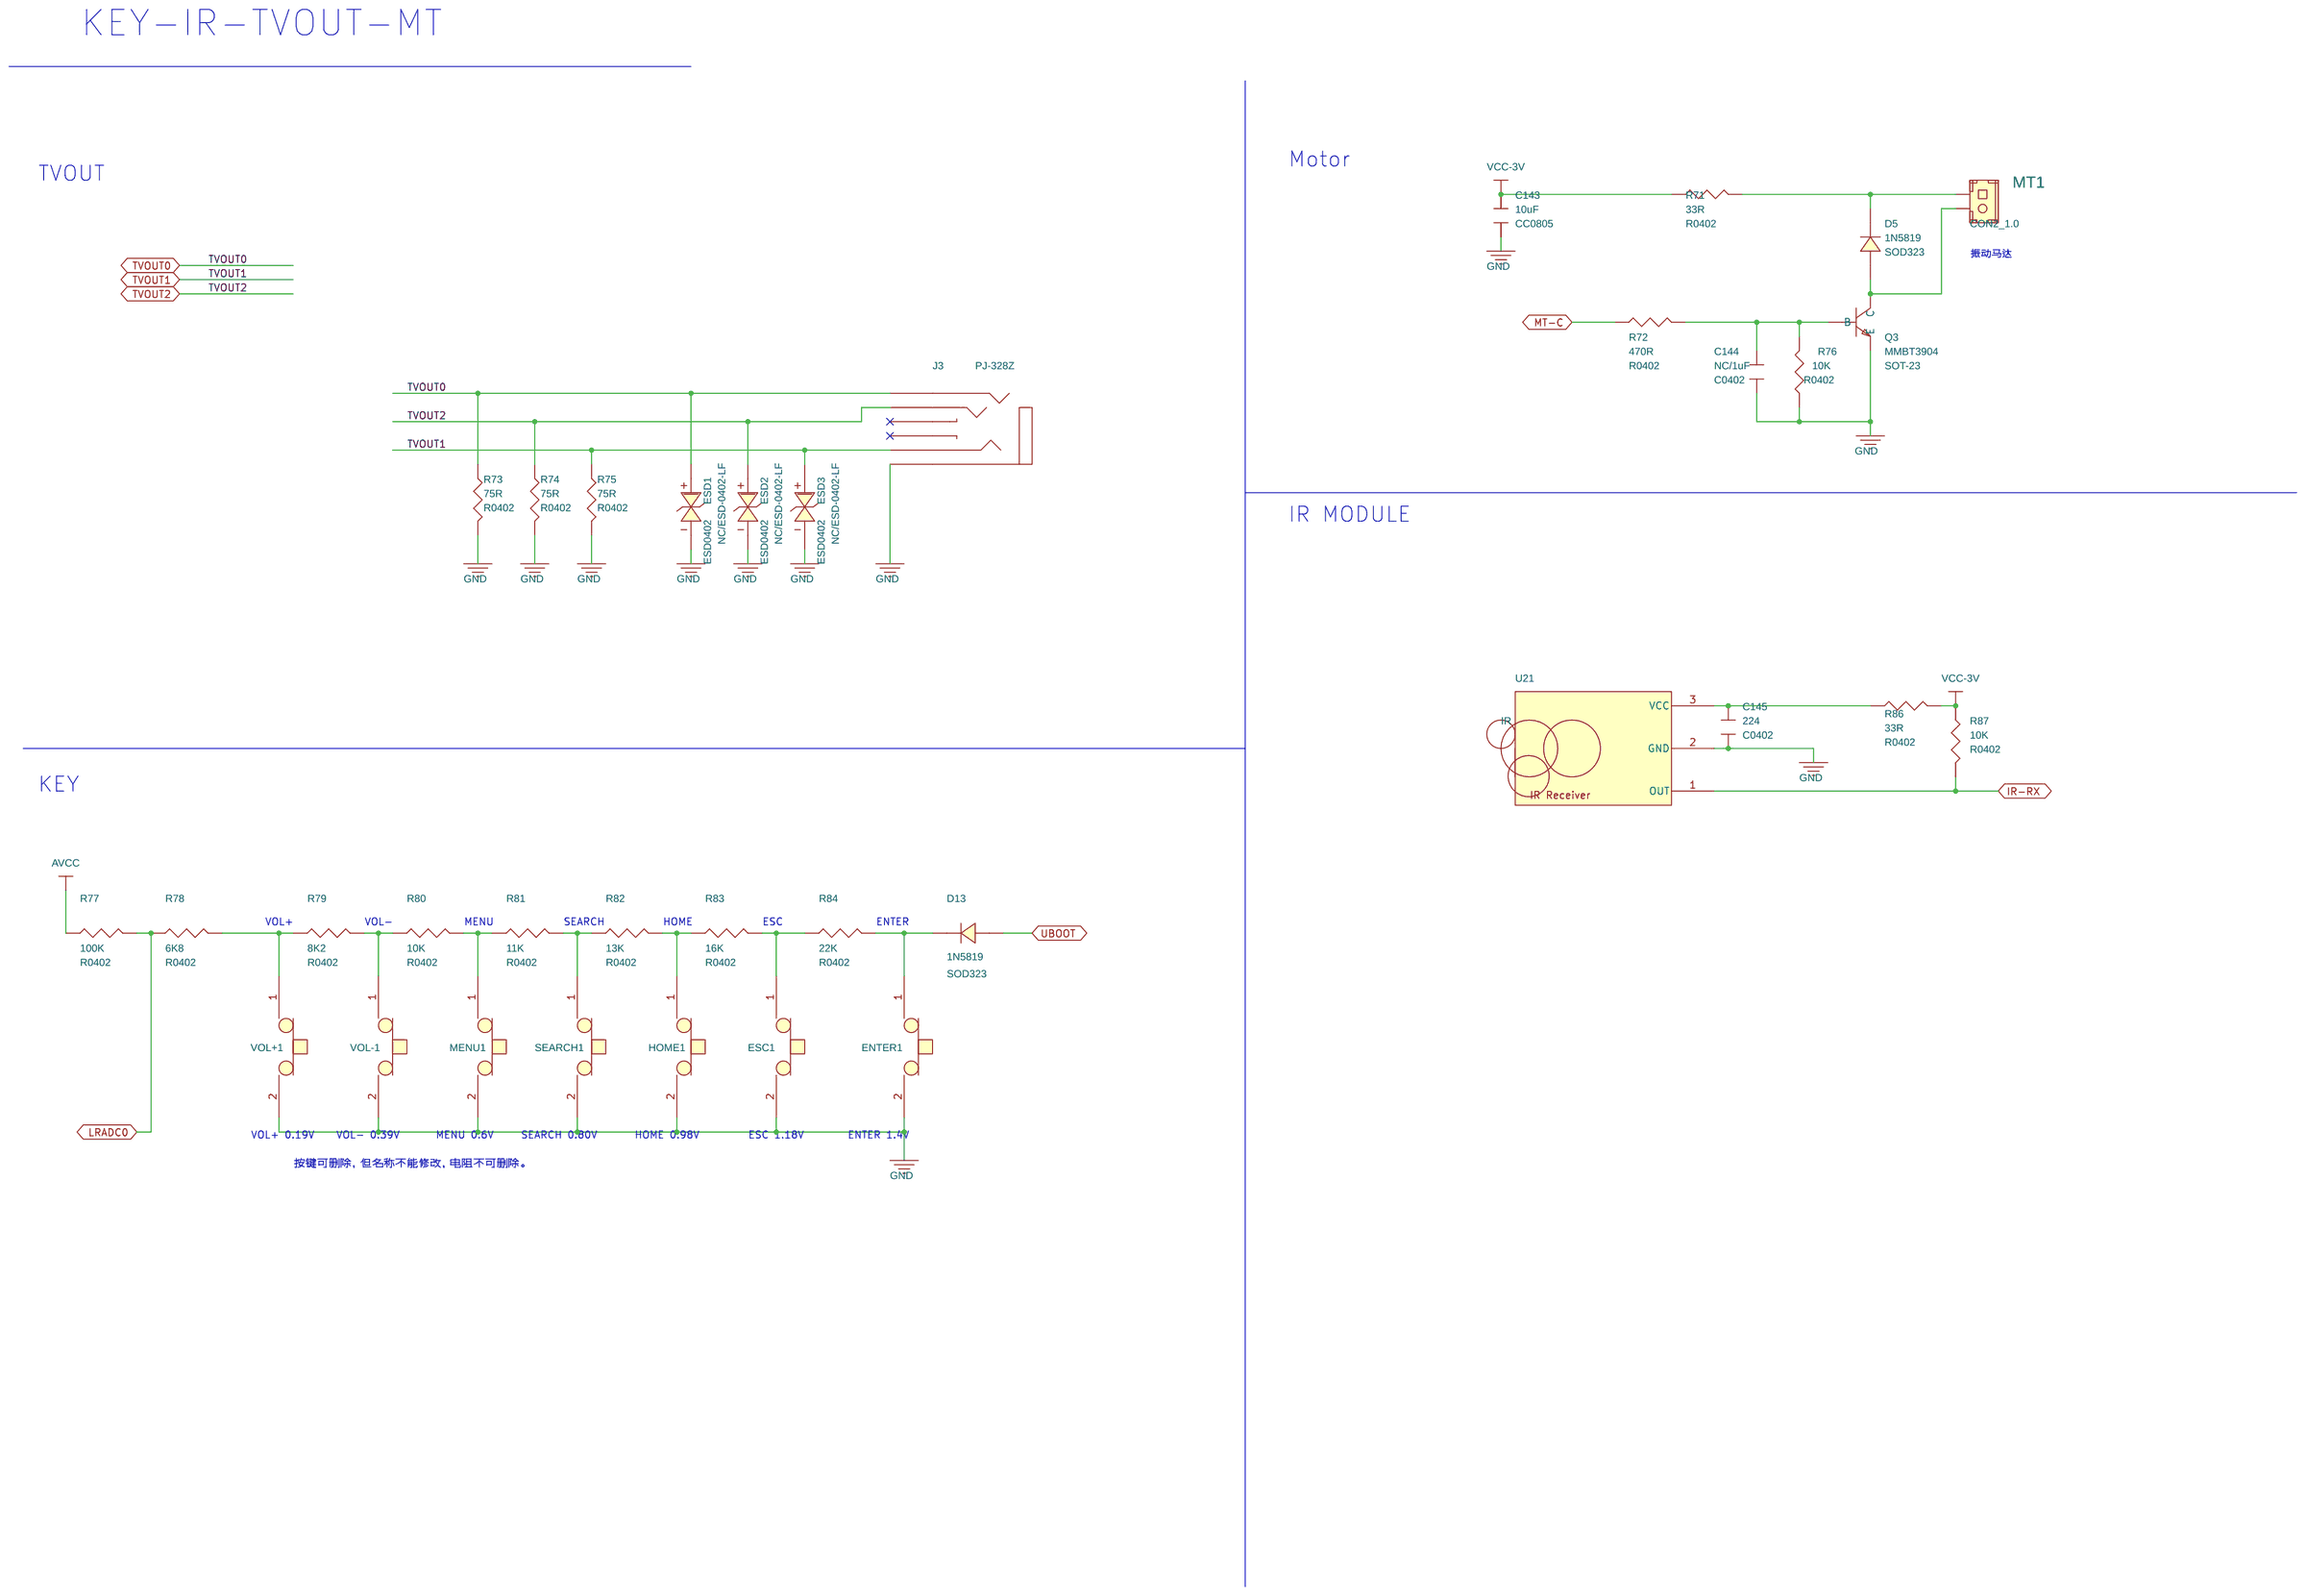
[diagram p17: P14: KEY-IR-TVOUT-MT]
19 P08: DDR3 16bit x 2pcs: size A3; note: DDR3 16bit*2pcs
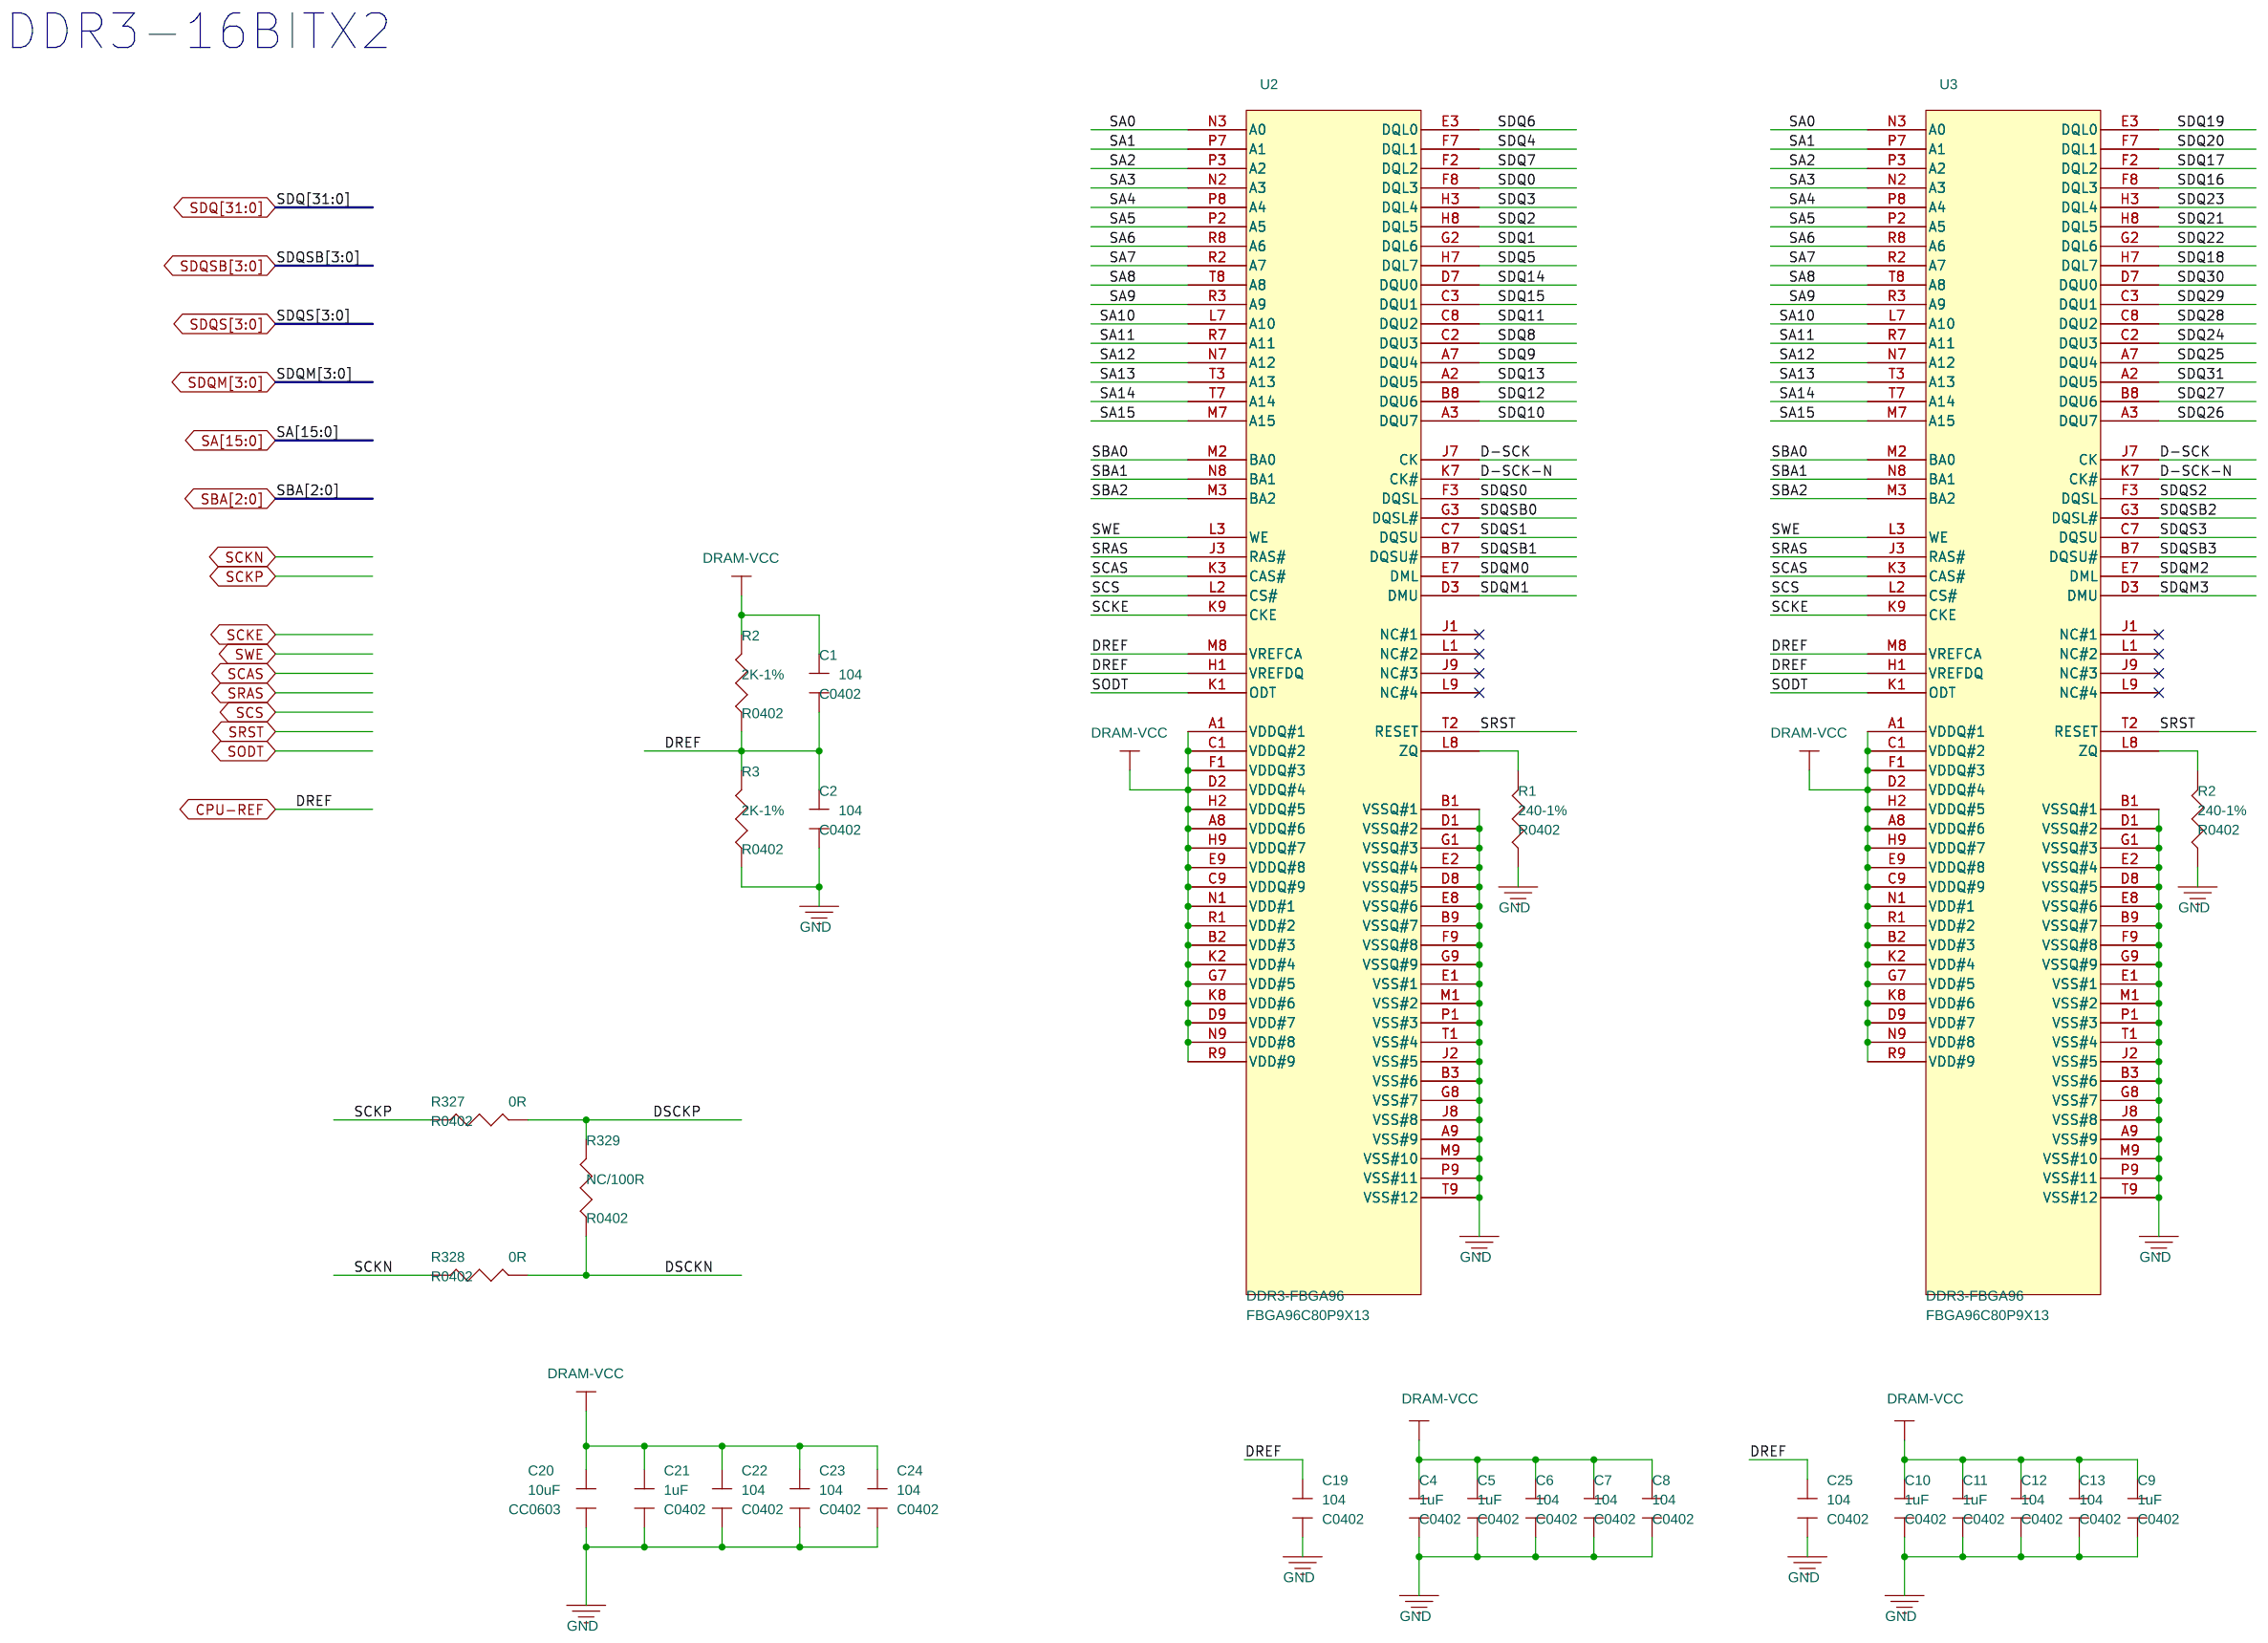
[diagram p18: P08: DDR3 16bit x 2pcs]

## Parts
sheet P07: DDR3 8bit x 4pcs
C1  104  [C0402]
C2  104  [C0402]
C4  1uF  [C0402]
C5  104  [C0402]
C6  104  [C0402]
C7  104  [C0402]
C8  1uF  [C0402]
C9  104  [C0402]
C10  104  [C0402]
C11  104  [C0402]
C12  1uF  [C0402]
C13  104  [C0402]
C14  104  [C0402]
C15  104  [C0402]
C16  1uF  [C0402]
C17  104  [C0402]
C18  104  [C0402]
C19  104  [C0402]
C20  10uF  [CC0603]
C21  1uF  [C0402]
C22  104  [C0402]
C23  104  [C0402]
C24  104  [C0402]
C25  104  [C0402]
C26  104  [C0402]
C27  104  [C0402]
C28  104  [C0402]
R2  2K-1%  [R0402]
R3  2K-1%  [R0402]
R4  240-1%  [R0402]
R5  240-1%  [R0402]
R6  240-1%  [R0402]
R7  240-1%  [R0402]
R8  0R  [R0402]
R9  0R  [R0402]
R326  NC/100R  [R0402]
U2  DDR3x8  [FBGA78P0_8B7_5X11]
U3  DDR3x8  [FBGA78P0_8B7_5X11]
U4  DDR3x8  [FBGA78P0_8B7_5X11]
U5  DDR3x8  [FBGA78P0_8B7_5X11]
sheet P08: DDR3 16bit x 2pcs
C1#2  104  [C0402]
C2#2  104  [C0402]
C4#2  1uF  [C0402]
C5#2  1uF  [C0402]
C6#2  104  [C0402]
C7#2  104  [C0402]
C8#2  104  [C0402]
C9#2  1uF  [C0402]
C10#2  1uF  [C0402]
C11#2  1uF  [C0402]
C12#2  104  [C0402]
C13#2  104  [C0402]
C19#2  104  [C0402]
C20#2  10uF  [CC0603]
C21#2  1uF  [C0402]
C22#2  104  [C0402]
C23#2  104  [C0402]
C24#2  104  [C0402]
C25#2  104  [C0402]
R1#2  240-1%  [R0402]
R2#2  2K-1%  [R0402]
R3#2  2K-1%  [R0402]
R327  0R  [R0402]
R328  0R  [R0402]
R329  NC/100R  [R0402]
sheet P09: BESIDE CPU
C44  4.7uF  [C0603]
C45  104  [C0402]
C46  104  [C0402]
C47  4.7uF  [C0603]
C48  1uF  [C0402]
C49  1uF  [C0402]
C50  104  [C0402]
C51  104  [C0402]
C52  104  [C0402]
C53  12pF-1%  [C0402]
C54  12pF-1%  [C0402]
C55  10uF  [CC0805]
C56  1uF  [C0402]
C57  1uF  [C0402]
C58  1uF  [C0402]
C59  1uF  [C0402]
C60  104  [C0402]
C61  104  [C0402]
C62  12pF-1%  [C0402]
C63  12pF-1%  [C0402]
C64  10uF  [CC0805]
C65  1uF  [C0402]
C66  1uF  [C0402]
C67  104  [C0402]
C68  104  [C0402]
C69  104  [C0402]
C70  10uF  [CC0805]
C71  104  [C0402]
C72  4.7uF  [C0603]
C73  104  [C0402]
C74  1uF  [C0402]
C75  104  [C0402]
C76  104  [C0402]
C77  104  [C0402]
C78  104  [C0402]
C79  1uF  [C0402]
C80  104  [C0402]
C81  10uF  [CC0805]
C82  104  [C0402]
C83  10uF  [CC0805]
C84  104  [C0402]
C85  102  [C0402]
C86  104  [C0402]
C87  10uF  [CC0805]
C88  1uF  [C0402]
C89  1uF  [C0402]
C90  1uF  [C0402]
C91  1uF  [C0402]
C92  104  [C0402]
C93  104  [C0402]
C94  104  [C0402]
C95  104  [C0402]
C96  104  [C0402]
C97  104  [C0402]
R16  10M-1%  [R0402]
R17  0R 5%  [R0402]
R18  200k 1%  [R0402]
R19  0R 5%  [R0402]
R20  2K  [R0402]
R21  2K  [R0402]
R22  2K  [R0402]
R23  2K  [R0402]
X1  24M_20pF_10PPM  [DSX321G]
X2  32.768K  [XCOL-SMD]
sheet P12: NAND&eMMC
C135  104  [C0402]
C136  104  [C0402]
C137  104  [C0402]
C138  104  [C0402]
C139  104  [C0402]
C192  104  [C0402]
C208  NC  [C0402]
C209  104  [C0402]
C210  104  [C0402]
C219  104  [C0402]
C230  104  [C0402]
C393  1uF  [C0402]
C394  4.7uF  [C0402]
C395  104  [C0402]
C396  NC  [C0402]
R48  NC  [R0402]
R49  NC  [R0402]
R50  10K  [R0402]
R51  10K  [R0402]
R52  10K  [R0402]
R53  NC  [R0402]
R54  NC  [R0402]
R137  0R  [R0402]
R157  27R  [R0402]
R290  NC/0R  [R0402]
R292  NC/0R  [R0402]
R294  NC/0R  [R0402]
R296  NC/0R  [R0402]
R298  NC/0R  [R0402]
R299  0R  [R0402]
R300  10K  [R0402]
R301  10K  [R0402]
R302  10K  [R0402]
R303  10K  [R0402]
R308  10K  [R0402]
R309  10K  [R0402]
R310  NC/0R  [R0402]
R311  0R  [R0402]
R312  NC/0R  [R0402]
R313  0R  [R0402]
U13  NAND FLASH X8  [TSOP-48]
U14  NAND FLASH X8  [TSOP-48]
U15  NAND FLASH x8  [LGA]
U16  NAND FLASH x8  [LGA]
U39  eMMC-BGA169  (section A)
sheet P14: KEY-IR-TVOUT-MT
C143  10uF  [CC0805]
C144  NC/1uF  [C0402]
C145  224  [C0402]
D5  1N5819  [SOD323]
D13  1N5819  [SOD323]
ENTER1  SW1 /BOOTS  [KEY-2]
ESC1  ESC1  [KEY-2]
ESD1  NC/ESD-0402-LF  [ESD0402]
ESD2  NC/ESD-0402-LF  [ESD0402]
ESD3  NC/ESD-0402-LF  [ESD0402]
HOME1  HOME1  [KEY-2]
J3  PJ-328Z  [PJ-320D]
MENU1  VOL+1  [KEY-2]
MT1  CON2_1.0  [CON2_1.0]
Q3  MMBT3904  [SOT-23]
R71  33R  [R0402]
R72  470R  [R0402]
R73  75R  [R0402]
R74  75R  [R0402]
R75  75R  [R0402]
R76  10K  [R0402]
R77  100K  [R0402]
R78  6K8  [R0402]
R79  8K2  [R0402]
R80  10K  [R0402]
R81  11K  [R0402]
R82  13K  [R0402]
R83  16K  [R0402]
R84  22K  [R0402]
R86  33R  [R0402]
R87  10K  [R0402]
SEARCH1  VOL-1  [KEY-2]
U21  IR_MODULE  [IR]
VOL+1  NEXT1  [KEY-2]
VOL-1  PREV1  [KEY-2]
sheet P15: CARD-DEBUG-GS
C146  10uF  [CC0805]
C147  104  [C0402]
C148  104  [C0402]
C149  104  [C0402]
C150  1uF  [C0402]
C151  104  [C0402]
C152  104  [C0402]
ESD4  ESD-0402-LF  [ESD0402]
ESD5  ESD-0402-LF  [ESD0402]
ESD6  ESD-0402-LF  [ESD0402]
ESD7  ESD-0402-LF  [ESD0402]
ESD8  ESD-0402-LF  [ESD0402]
ESD9  ESD-0402-LF  [ESD0402]
J4  MICROSD/TF_SLOT  [MICROSD_SLOT]
R88  47K  [R0402]
R89  47K  [R0402]
R90  10K  [R0402]
R91  NC/0R 5%  [R0402]
R92  NC/10K  [R0402]
R93  NC/10K  [R0402]
R94  NC/10K  [R0402]
R325  2R2  [R0402]
TP1  T_POINT_R  [tp_pad]
TP2  T_POINT_R  [tp_pad]
TP3  T_POINT_R  [tp_pad]
TP4  T_POINT_R  [tp_pad]
TP5  T_POINT_R  [tp_pad]
TP6  T_POINT_R  [tp_pad]
U22  BMA250  [LGA-12]
U23  MMA8452Q/LIS3DH  [QFN16-PT0_5-3X3H1A]
U24  MMA7660FC  [IC-DFN10]
sheet P19: HP-MIC-SPK
C193  104  [C0402]
C194  104  [C0402]
C195  104  [C0402]
C196  1uF  [C0402]
C197  394  [C0402]
C198  2.2uF  [C0603]
C199  102  [C0402]
C200  1uF  [C0402]
C201  394  [C0402]
C202  2.2uF  [C0603]
C203  102  [C0402]
C204  4.7uF  [C0603]
C205  4.7uF  [C0603]
C206  104  [C0402]
C207  332  [C0402]
CN1  LEFT-SPEAKER  [SPK-SMD]
CN2  RIGHT-SPEAKER  [SPK-SMD]
ESD14  ESD-0402-LF  [ESD0402]
ESD15  ESD-0402-LF  [ESD0402]
ESD16  ESD-0402-LF  [ESD0402]
FB1  600R-100M  [L0805]
FB2  600R-100M  [L0805]
J7  PJ-328Z  [PJ-320D]
MIC1  Micphone  [MIC_450X250]
Q9  MMBT3904  [SOT-23]
R144  22R  [R0402]
R145  22R  [R0402]
R146  22R  [R0402]
R147  NC/100K  [R0402]
R148  20K  [R0402]
R149  33K  [R0402]
R150  10K  [R0402]
R151  20K  [R0402]
R152  510K  [R0402]
R153  20K  [R0402]
R154  33K  [R0402]
R155  2K  [R0402]
R156  4K3  [R0402]
R323  0R  [R0402]
U30  LM4890  [MSOP8]
U31  LM4890  [MSOP8]

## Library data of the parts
C1 C1#2 C2 C2#2 C150 = CAPACITOR_0: PAGE: 1
C4 C4#2 C5 C5#2 C6 C6#2 C7 C7#2 C8 C8#2 C9 C9#2 C10 C10#2 C11 C11#2 C12 C12#2 C13 C13#2 C14-C19 C19#2 C20 C20#2 C21 C21#2 C22 C22#2 C23 C23#2 C24 C24#2 C25 C25#2 C26-C28 C44-C68 C70 C75-C82 C87-C93 C95 C97 C135-C139 C144 C192 C206 C208-C210 C219 C230 C393-C396 = CAPACITOR_0: PAGE: 2
R2 R2#2 R3 R3#2 R326 R329 = ?_0
R1#2 R4-R7 R16-R23 R48-R54 R86-R91 R137 R157 R290 R292 R294 R296 R298-R303 R308-R313 = R
R8 R9 R77-R84 R327 R328 = R1_0805
U2-U5 = DDR3x8-FBGA78
C69 C71-C74 C85 C143 C196-C205 C207 = CAPACITOR_0
C83 C145 C193-C195 = CAPACITOR
C84 C86 C94 C96 C146 = CAPACITOR_0: PAGE: 3
X1 = CRYSTAL-4_3: Crystal 24MHz 20pF 10ppm  -30 to +85; PART NUMBER: 7M24000004; SPREADWIN PN: U3000019A; Vendor: TXC
X2 = CRYSTAL_XCOL-3_0
U13 U14 = NAND_FLASH_X8
U15 U16 = toggle_nand_2
U39 = eMMC-BGA169
D5 D13 = DIODE: Diode,Schottky,1N5819HW,40V,500mA,450mV,SOD-323; Supplier: DIODES; Supplier P/N: 1N5819HW
ENTER1 ESC1 HOME1 MENU1 SEARCH1 VOL+1 VOL-1 = KEY-2PIN_0
ESD1-ESD9 ESD14-ESD16 = DIODE_TVS_LC_2: RoHS ESD-0603-LF SMT 0402; PN: 450-0001-216; chinese name: ¬ðªi§l¦¬¾¹; ㄑ莱坝: ¤O¼Ý; ³æ¦ì: PCS
J3 J7 = HP_JACK_1
MT1 = ~WB_1X2
Q3 Q9 = NPN
R71-R76 R144-R156 R323 = RESISTOR
U21 = IR_Module_4
C147-C149 C151 C152 = CAPACITOR_1: PAGE: 1
J4 = SDMMC_SLOT_11
R92-R94 R325 = R: CHIP RESISTOR 1/16W 0402 ROHS; Tolerance: +/-5%
TP1-TP6 = T_POINT_R
U22 = BMA222
U23 = BMA222_0
U24 = MMA7660FC
CN1 CN2 = SPEAKER
FB1 FB2 = INDUCTOR
MIC1 = Micphone
U30 U31 = LY8006

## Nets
AVCC: R77.1 ; also on sheet 1 2 8
VCCQ: C209.2 C210.2 R137.2 U39.AA3(VDDQM4) U39.AA5(VDDQM5) U39.K6(VDDQM1) U39.W4(VDDQM2) U39.Y4(VDDQM3)
CARD-VCC: C52.2 C64.2 C65.2 C66.2 C67.2 C68.2 C77.2 C78.2 C79.2 C80.2 C86.2 C94.2 C96.2 C97.2 C135.2 C136.2 C137.2 C138.2 C143.2 C147.2 C148.2 C149.2 C150.2 C151.2 C219.2 C230.2 R20.1 R21.1 R22.1 R23.1 R50.2 R51.2 R52.1 R53.1 R71.2 R86.2 R87.1 R88.2 R89.2 R90.1 R92.1 R93.1 R137.1 R147.1 R300.1 R301.1 R302.1 R303.1 R308.1 R309.1 R311.1 R313.1 R325.2 U13.1(RES#) U13.12(VCC1) U13.24(NC9) U13.34(NC15) U13.37(VCC2) U13.39(NC17) U14.1(RES#) U14.12(VCC1) U14.24(NC9) U14.34(NC15) U14.37(VCC2) U14.39(NC17) U15.B7(VCC1) U15.M7(VCC2) U15.N2(VCCQ6) U15.N8(VCCQ5) U15.OB9(VCCQ3) U15.OD1(VCCQ1) U15.OF1(VCCQ2) U15.OG9(VCCQ4) U16.B7(VCC1) U16.M7(VCC2) U16.N2(VCCQ6) U16.N8(VCCQ5) U16.OB9(VCCQ3) U16.OD1(VCCQ1) U16.OF1(VCCQ2) U16.OG9(VCCQ4) U22.3(VDIO) U22.7(VDD) U23.1(VDDIO) U23.14(VDD) U24.3(AVDD) U24.9(SVDD) U39.M6(VDDM1) U39.N5(VDDM2) U39.T10(VDDM3) U39.U9(VDDM4) ; also on sheet 1 2 3 4 5 8 10 11
CLK32K-IN: C54.2 R16.1 X2.1 ; also on sheet 2
CLK32K-OUT: C63.2 R16.2 X2.2 ; also on sheet 2
CPUVDD: C87.2 C88.2 C89.2 C90.2 C91.2 C92.2 C93.2 ; also on sheet 5 8
CSI-IOVDD: C75.2 C76.2 ; also on sheet 5 8 10
DLLVDD: C44.2 C45.2 C46.2 C55.2 C56.2 C57.2 C58.2 C59.2 C60.2 C61.2 C95.2 ; also on sheet 5 8
DRAM-VCC: C1.1 C1.2 C1#2.1 C1#2.2 C2.1 C2.2 C2#2.1 C2#2.2 C4.1 C4.2 C4#2.1 C4#2.2 C5.1 C5.2 C5#2.1 C5#2.2 C6.1 C6.2 C6#2.1 C6#2.2 C7.1 C7.2 C7#2.1 C7#2.2 C8.1 C8.2 C8#2.1 C8#2.2 C9.1 C9.2 C9#2.1 C9#2.2 C10.1 C10.2 C10#2.1 C10#2.2 C11.1 C11.2 C11#2.1 C11#2.2 C12.1 C12.2 C12#2.1 C12#2.2 C13.1 C13.2 C13#2.1 C13#2.2 C14.1 C14.2 C15.1 C15.2 C16.1 C16.2 C17.1 C17.2 C18.1 C18.2 C19.1 C19.2 C19#2.1 C19#2.2 C20.1 C20.2 C20#2.1 C20#2.2 C21.1 C21.2 C21#2.1 C21#2.2 C22.1 C22.2 C22#2.1 C22#2.2 C23.1 C23.2 C23#2.1 C23#2.2 C24.1 C24.2 C24#2.1 C24#2.2 C25.1 C25.2 C25#2.1 C25#2.2 C26.1 C26.2 C27.1 C27.2 C28.1 C28.2 C44.1 C45.1 C46.1 C47.1 C47.2 C48.1 C48.2 C49.1 C49.2 C50.1 C50.2 C51.1 C51.2 C52.1 C53.1 C54.1 C55.1 C56.1 C57.1 C58.1 C59.1 C60.1 C61.1 C62.1 C63.1 C64.1 C65.1 C66.1 C67.1 C68.1 C69.1 C70.1 C71.1 C72.1 C73.1 C75.1 C76.1 C77.1 C78.1 C79.1 C80.1 C81.1 C82.1 C83.1 C84.1 C85.1 C86.1 C87.1 C88.1 C89.1 C90.1 C91.1 C92.1 C93.1 C94.1 C95.1 C96.1 C97.1 C135.1 C136.1 C137.1 C138.1 C139.1 C143.1 C144.1 C145.1 C146.1 C147.1 C148.1 C149.1 C150.1 C151.1 C152.2 C192.1 C193.1 C194.1 C195.1 C196.2 C198.1 C200.2 C202.1 C208.1 C209.1 C210.1 C219.1 C230.1 C393.1 C394.1 C395.1 C396.1 ENTER1.2 ESC1.2 ESD1.2 ESD2.2 ESD3.2 ESD4.2 ESD5.2 ESD6.2 ESD7.2 ESD8.2 ESD9.2 ESD14.2 ESD15.2 ESD16.2 HOME1.2 J3.6 J4.6(VSS2) J4.10(GND) MENU1.2 Q3.2(E) Q9.2(E) R1#2.1 R1#2.2 R2.1 R2.2 R2#2.1 R2#2.2 R3.1 R3.2 R3#2.1 R3#2.2 R4.1 R4.2 R5.1 R6.1 R7.1 R9.2 R18.1 R19.2 R54.2 R73.2 R74.2 R75.2 R76.2 R91.2 R94.1 R152.2 R326.1 SEARCH1.2 U2.A1(VDDQ#1) U2.A2(DQU5) U2.A3(DQU7) U2.A8(VDDQ#6) U2.A9(VSS#9) U2.B1(VSSQ#1) U2.B2(VDD#3) U2.B3(VSS#6) U2.B8(DQU6) U2.B9(VSSQ#7) U2.C1(VDDQ#2) U2.C2(DQU3) U2.C3(DQU1) U2.C8(DQU2) U2.C9(VDDQ#9) U2.D1(VSSQ#2) U2.D2(VDDQ#4) U2.D7(DQU0) U2.D8(VSSQ#5) U2.D9(VDD#7) U2.E1(VSS#1) U2.E2(VSSQ#4) U2.E3(DQL0) U2.E8(VSSQ#6) U2.E9(VDDQ#8) U2.F1(VDDQ#3) U2.F2(DQL2) U2.F3(DQSL) U2.F8(DQL3) U2.F9(VSSQ#8) U2.G1(VSSQ#3) U2.G2(DQL6) U2.G7(VDD#5) U2.G8(VSS#7) U2.G9(VSSQ#9) U2.H1(VREFDQ) U2.H2(VDDQ#5) U2.H3(DQL4) U2.H8(DQL5) U2.H9(VDDQ#7) U2.J1(NC#1) U2.J2(VSS#5) U2.J3(RAS#) U2.J8(VSS#8) U2.J9(NC#3) U2.K1(ODT) U2.K2(VDD#4) U2.K8(VDD#6) U2.K9(CKE) U2.L1(NC#2) U2.L2(CS#) U2.L3(WE) U2.L8(ZQ) U2.L9(NC#4) U2.M1(VSS#2) U2.M2(BA0) U2.M3(BA2) U2.M8(VREFCA) U2.M9(VSS#10) U2.N1(VDD#1) U2.N2(A3) U2.N8(BA1) U2.N9(VDD#8) U2.P1(VSS#3) U2.P2(A5) U2.P3(A2) U2.P8(A4) U2.P9(VSS#11) U2.R1(VDD#2) U2.R2(A7) U2.R3(A9) U2.R8(A6) U2.R9(VDD#9) U2.T1(VSS#4) U2.T2(RESET) U2.T8(A8) U2.T9(VSS#12) U3.A1(VDDQ#1) U3.A2(DQU5) U3.A8(VDDQ#6) U3.A9(VSS#9) U3.B1(VSSQ#1) U3.B2(VDD#3) U3.B3(VSS#6) U3.B8(DQU6) U3.B9(VSSQ#7) U3.C1(VDDQ#2) U3.C2(DQU3) U3.C7(DQSU) U3.C9(VDDQ#9) U3.D1(VSSQ#2) U3.D2(VDDQ#4) U3.D7(DQU0) U3.D8(VSSQ#5) U3.D9(VDD#7) U3.E1(VSS#1) U3.E2(VSSQ#4) U3.E3(DQL0) U3.E7(DML) U3.E8(VSSQ#6) U3.E9(VDDQ#8) U3.F1(VDDQ#3) U3.F2(DQL2) U3.F3(DQSL) U3.F8(DQL3) U3.F9(VSSQ#8) U3.G1(VSSQ#3) U3.G2(DQL6) U3.G7(VDD#5) U3.G8(VSS#7) U3.G9(VSSQ#9) U3.H1(VREFDQ) U3.H2(VDDQ#5) U3.H3(DQL4) U3.H9(VDDQ#7) U3.J1(NC#1) U3.J2(VSS#5) U3.J3(RAS#) U3.J8(VSS#8) U3.J9(NC#3) U3.K1(ODT) U3.K2(VDD#4) U3.K8(VDD#6) U3.K9(CKE) U3.L1(NC#2) U3.L2(CS#) U3.L3(WE) U3.L8(ZQ) U3.L9(NC#4) U3.M1(VSS#2) U3.M2(BA0) U3.M3(BA2) U3.M8(VREFCA) U3.M9(VSS#10) U3.N1(VDD#1) U3.N2(A3) U3.N8(BA1) U3.N9(VDD#8) U3.P1(VSS#3) U3.P2(A5) U3.P3(A2) U3.P8(A4) U3.P9(VSS#11) U3.R1(VDD#2) U3.R2(A7) U3.R3(A9) U3.R8(A6) U3.R9(VDD#9) U3.T1(VSS#4) U3.T2(RESET) U3.T8(A8) U3.T9(VSS#12) U4.A1(VSS1) U4.A2(VDD1) U4.A8(VSS2) U4.A9(VDD2) U4.B1(VSS3) U4.B2(VSSQ1) U4.B3(DQ0) U4.B7(DM/TDQS) U4.B8(VSSQ2) U4.B9(VDDQ1) U4.C1(VDDQ2) U4.C2(DQ2) U4.C3(DQS) U4.C8(DQ3) U4.C9(VSSQ3) U4.D1(VSSQ4) U4.D2(DQ6) U4.D7(VDD3) U4.D8(VSS4) U4.D9(VSSQ5) U4.E1(VREFDQ) U4.E2(VDDQ3) U4.E3(DQ4) U4.E9(VDDQ4) U4.F2(VSS5) U4.F3(\\~{RA}S) U4.F8(VSS6) U4.G1(ODT) U4.G2(VDD4) U4.G7(\\~{C}K) U4.G8(VDD5) U4.G9(CKE) U4.H2(\\~{C}S) U4.H3(\\~{W}E) U4.J1(VSS7) U4.J2(BA0) U4.J3(BA2) U4.J8(VREFCA) U4.J9(VSS8) U4.K1(VDD6) U4.K2(A3) U4.K8(BA1) U4.K9(VDD7) U4.L1(VSS9) U4.L2(A5) U4.L3(A2) U4.L8(A4) U4.L9(VSS10) U4.M1(VDD8) U4.M2(A7) U4.M3(A9) U4.M8(A6) U4.M9(VDD9) U4.N1(VSS11) U4.N2(\\~{RESET}) U4.N8(A8) U4.N9(VSS12) U5.A1(VSS1) U5.A2(VDD1) U5.A8(VSS2) U5.A9(VDD2) U5.B1(VSS3) U5.B2(VSSQ1) U5.B3(DQ0) U5.B8(VSSQ2) U5.B9(VDDQ1) U5.C1(VDDQ2) U5.C2(DQ2) U5.C3(DQS) U5.C7(DQ1) U5.C9(VSSQ3) U5.D1(VSSQ4) U5.D7(VDD3) U5.D8(VSS4) U5.D9(VSSQ5) U5.E1(VREFDQ) U5.E2(VDDQ3) U5.E8(DQ5) U5.E9(VDDQ4) U5.F2(VSS5) U5.F3(\\~{RA}S) U5.F8(VSS6) U5.G1(ODT) U5.G2(VDD4) U5.G7(\\~{C}K) U5.G8(VDD5) U5.G9(CKE) U5.H2(\\~{C}S) U5.H3(\\~{W}E) U5.J1(VSS7) U5.J2(BA0) U5.J3(BA2) U5.J8(VREFCA) U5.J9(VSS8) U5.K1(VDD6) U5.K2(A3) U5.K8(BA1) U5.K9(VDD7) U5.L1(VSS9) U5.L2(A5) U5.L3(A2) U5.L8(A4) U5.L9(VSS10) U5.M1(VDD8) U5.M2(A7) U5.M3(A9) U5.M8(A6) U5.M9(VDD9) U5.N1(VSS11) U5.N2(\\~{RESET}) U5.N8(A8) U5.N9(VSS12) U13.2(NC2) U13.13(VSS1) U13.23(NC8) U13.25(NC10) U13.36(VSS2) U13.48(NC22) U14.2(NC2) U14.13(VSS1) U14.23(NC8) U14.25(NC10) U14.36(VSS2) U14.48(NC22) U15.B3(VSS1) U15.F7(VSSQ5) U15.L4(VSSQ6) U15.M3(VSS2) U15.OB1(VSSQ1) U15.OD9(VSSQ3) U15.OF9(VSSQ4) U15.OG1(VSSQ2) U16.B3(VSS1) U16.F7(VSSQ5) U16.L4(VSSQ6) U16.M3(VSS2) U16.OB1(VSSQ1) U16.OD9(VSSQ3) U16.OF9(VSSQ4) U16.OG1(VSSQ2) U21.2(GND) U22.4(NC) U22.8(GNDIO) U22.9(GND) U23.5(GND1) U23.10(GND2) U23.12(GND3) U24.1(RESERVED) U24.4(AVSS) U24.8(DVSS) U30.7(GND) U31.7(GND) U39.AA4(VSSQM4) U39.AA6(VSSQM5) U39.K4(VSSQM1) U39.M7(VSSM1) U39.P5(VSSM2) U39.R10(VSSM3) U39.U8(VSSM4) U39.Y2(VSSQM2) U39.Y5(VSSQM3) VOL+1.2 VOL-1.2 X1.2(GND) X1.4(GND) X2.3(Shield) ; also on sheet 1 2 3 4 5 8 10 11
DSCKN: R328.2 R329.1
DSCKP: R327.2 R329.2
eMMC-CLK: C396.2 R157.2 U39.W6(CLKM)
eMMC-RST: C395.2 R309.2 R310.2 U39.U5(RSTN)
HPBP: C81.2 C82.2 ; also on sheet 2
HPCOM: ESD16.1 J7.6 R144.1 R323.2 ; also on sheet 2
HPCOMFB: R323.1 ; also on sheet 2
HPIN: J7.1 R151.1
HPL: C197.2 ESD14.1 J7.2 R146.1 ; also on sheet 2
HPR: C201.2 ESD15.1 J7.5 R145.1 ; also on sheet 2
IPSOUT: FB1.2 FB2.2 ; also on sheet 1 4 8 11
IR-RX: R87.2 U21.1(OUT) ; also on sheet 2
JTAG-CK: TP4.1(TP) ; also on sheet 2
JTAG-DI: TP6.1(TP) ; also on sheet 2
JTAG-DO: TP5.1(TP) ; also on sheet 2
JTAG-MS: TP3.1(TP) ; also on sheet 2
JTAG-SEL: R91.1 ; also on sheet 2
LRADC0: C85.2 R77.2 R78.1 ; also on sheet 2
MICIN1: C206.2 ; also on sheet 2
MICM: C74.1 C204.1 C205.1 C207.2 MIC1.2(-) R19.1
MT-C: R72.2 ; also on sheet 2
NALE: U13.17(ALE) U14.17(ALE) U15.C2(ALE) U16.C2(ALE) ; also on sheet 5
NAND-DQS: R299.2 U13.35(NC16)
NCE0#: U13.9(CE1#) U16.A6(~{CE}) ; also on sheet 5
NCE1#: U13.10(CE2#) ; also on sheet 5
NCE2#: U13.14(CE3#) U14.9(CE1#) U15.A6(~{CE}) ; also on sheet 5
NCE3#: U13.15(CE4#) U14.10(CE2#) ; also on sheet 5
NCLE: U13.16(CLE) U14.16(CLE) U15.A4(CLE) U16.A4(CLE) ; also on sheet 5
ND0: R300.2 R312.1 U13.29(IO0) U14.29(IO0) U15.G4(DQ0) U16.G4(DQ0) U39.H3(DAT0) ; also on sheet 5
ND1: R298.1 R301.2 U13.30(IO1) U14.30(IO1) U15.H3(DQ1) U16.H3(DQ1) U39.H4(DAT1) ; also on sheet 5
ND2: R296.1 R302.2 U13.31(IO2) U14.31(IO2) U15.J4(DQ2) U16.J4(DQ2) U39.H5(DAT2) ; also on sheet 5
ND3: R294.1 R303.2 U13.32(IO3) U14.32(IO3) U15.K3(DQ3) U16.K3(DQ3) U39.J2(DAT3) ; also on sheet 5
ND4: U13.41(IO4) U14.41(IO4) U15.L6(DQ4) U16.L6(DQ4) ; also on sheet 5
ND5: U13.42(IO5) U14.42(IO5) U15.K7(DQ5) U16.K7(DQ5) ; also on sheet 5
ND6: U13.43(IO6) U14.43(IO6) U15.J6(DQ6) U16.J6(DQ6) ; also on sheet 5
ND7: U13.44(IO7) U14.44(IO7) U15.H7(DQ7) U16.H7(DQ7) ; also on sheet 5
NDQS: R299.1 R310.1 U14.35(NC16) U15.H5(DQS) U16.H5(DQS) ; also on sheet 5
NRB0#: R49.2 R51.1 R290.1 R308.2 U13.7(RB1#) U16.E6(R/B) U39.W5(CMD) ; also on sheet 5
NRB1#: R48.2 R50.1 R157.1 R292.1 U13.4(RB4#) U13.5(RB3#) U14.6(RB2#) U14.7(RB1#) U15.E6(R/B) ; also on sheet 5
NRE#: U13.8(RE#) U14.8(RE#) U15.C8(~{RE}) U16.C8(~{RE}) ; also on sheet 5
NWE#: U13.18(WE#) U14.18(WE#) U15.E4(~{WE}) U16.E4(~{WE}) ; also on sheet 5
NWP: C139.2 R52.2 U13.19(WP#) U14.19(WP#) U15.F3(~{WP}) U16.F3(~{WP})
OSC24MI: C53.2 X1.1(XIN) ; also on sheet 2
OSC24MO: R17.1 ; also on sheet 2
PA-SHDN#: R150.1 ; also on sheet 2
RESET#: C69.2 ; also on sheet 2 8
RTCVDD: C83.2 C84.2 ; also on sheet 2 8
SA0: U2.D3(DMU) U2.G3(DQSL#) U2.K3(CAS#) U2.N3(A0) U2.T3(A13) U3.B7(DQSU#) U3.G3(DQSL#) U3.K3(CAS#) U3.N3(A0) U3.T3(A13) U4.D3(\\~{DQ}S) U4.G3(\\~{CA}S) U4.K3(A0) U4.N3(A13) U5.D3(\\~{DQ}S) U5.G3(\\~{CA}S) U5.K3(A0) U5.N3(A13) ; also on sheet 5
SA1: U2.B7(DQSU#) U2.E7(DML) U2.H7(DQL7) U2.L7(A10) U2.P7(A1) U3.D3(DMU) U3.H7(DQL7) U3.L7(A10) U3.P7(A1) U4.E8(DQ5) U4.H7(A10/AP) U4.L7(A1) U5.B7(DM/TDQS) U5.H7(A10/AP) U5.L7(A1) ; also on sheet 5
SA11: U2.J7(CK) U2.M7(A15) U2.R7(A11) U3.J7(CK) U3.M7(A15) U3.R7(A11) U4.J7(A15) U4.M7(A11) U5.J7(A15) U5.M7(A11) ; also on sheet 5
SA12: U2.K7(CK#) U2.N7(A12) U2.T7(A14) U3.K7(CK#) U3.N7(A12) U3.T7(A14) U4.K7(A12/BC#) U4.N7(A14) U5.K7(A12/BC#) U5.N7(A14) ; also on sheet 5
SCKN: R9.1 R328.1 ; also on sheet 5
SCKP: R8.1 R327.1 ; also on sheet 5
SD0-CLK: J4.5(CLK) ; also on sheet 2
SD0-CMD: ESD7.1 J4.3(CMD) R89.1 ; also on sheet 2
SD0-D0: ESD6.1 J4.7(DAT0) ; also on sheet 2
SD0-D1: ESD5.1 J4.8(DAT1) ; also on sheet 2
SD0-D2: ESD9.1 J4.1(DAT2) ; also on sheet 2
SD0-D3: ESD8.1 J4.2(DAT3) ; also on sheet 2
SD0-DET: ESD4.1 J4.9(CD#) R88.1 ; also on sheet 2
SDQ20: R8.2 R326.2 U2.C7(DQSU) U2.F7(DQL1) U3.C3(DQU1) U3.F7(DQL1) U4.C7(DQ1) U4.F7(CK) U5.E3(DQ4) U5.F7(CK) ; also on sheet 5
SDQ21: R5.2 U3.H8(DQL5) U4.E7(DQ7) ; also on sheet 5
SDQ25: U3.A7(DQU4) U5.C8(DQ3) ; also on sheet 5
SDQ26: U3.A3(DQU7) U5.D2(DQ6) ; also on sheet 5
SDQ28: U2.A7(DQU4) U3.C8(DQU2) U5.E7(DQ7) ; also on sheet 5
tSD-CLK: R292.2 U13.40(NC18)
tSD-CMD: R290.2 U13.33(NC14)
tSD-D0: R312.2 U13.47(NC21)
tSD-D1: R298.2 U13.46(NC20)
tSD-D2: R296.2 R313.2 U13.45(NC19)
tSD-D3: R294.2 U13.27(NC12)
TVOUT0: ESD1.1 J3.1 R73.1 ; also on sheet 2
TVOUT1: ESD3.1 J3.5 R75.1 ; also on sheet 2
TVOUT2: ESD2.1 J3.2 R74.1 ; also on sheet 2
TWI1-SCK: R21.2 U22.12(SCX) U23.4(SCL) U24.6(SCL) ; also on sheet 2 10
TWI1-SDA: R20.2 U22.2(SDI) U23.6(SDA) U24.7(SDA) ; also on sheet 2 10
TWI2-SCK: R23.2 ; also on sheet 2 4
TWI2-SDA: R22.2 ; also on sheet 2 4
UART0-RX: TP2.1(TP) ; also on sheet 2
UART0-TX: TP1.1(TP) ; also on sheet 2
UBOOT: D13.1(A) ; also on sheet 2
VMIC: C204.2 R155.2 ; also on sheet 2
VPS: R53.2 R54.1 U13.38(VSS3) U14.38(VSS3)
VRA1: C74.2 ; also on sheet 2
VRA2: C72.2 C73.2 R18.2 ; also on sheet 2
VRP: C70.2 C71.2 ; also on sheet 2
N29939661: C146.2 J4.4(VDD) R325.1
N30478268: R48.1 R49.1 U13.6(RB2#)
N31275691: C62.2 R17.2 X1.3(XOUT)
N36939581: ESC1.1 R83.2 R84.1
N36939583: D13.2(K) ENTER1.1 R84.2
N36939604: R79.2 R80.1 VOL-1.1
N36939620: R81.2 R82.1 SEARCH1.1
N36939622: MENU1.1 R80.2 R81.1
N36939637: HOME1.1 R82.2 R83.1
N36939639: R78.2 R79.1 VOL+1.1
N38809696: D5.2(K) MT1.1 R71.1
N38809723: C144.2 Q3.1(B) R72.1 R76.1
N38809774: D5.1(A) MT1.2 Q3.3(C)
N40520036: C145.2 R86.1 U21.3(VCC)
N59213731: C203.1 CN2.1(-) R154.2 U31.5(VO1)
N59213733: C203.2 R153.2 R154.1 U31.4(IN-)
N59213739: Q9.3(C) R147.2 R150.2 U30.1(SHDN#) U31.1(SHDN#)
N59213747: C201.1 R153.1
N59213753: Q9.1(B) R151.2 R152.1
N59213757: C198.2 FB1.1 U30.6(VDD)
N59213770: C200.1 U31.2(BYPASS) U31.3(NC)
N59213778: C199.2 R148.2 R149.1 U30.4(IN-)
N59213780: C199.1 CN1.1(-) R149.2 U30.5(VO1)
N59213791: CN2.2(+) U31.8(VO2)
N59213812: C196.1 U30.2(BYPASS) U30.3(NC)
N59213822: C197.1 R148.1
N59213841: CN1.2(+) U30.8(VO2)
N59213852: C202.2 FB2.1 U31.6(VDD)
N59216514: C205.2 R155.1 R156.2
N59216596: C206.1 C207.1 MIC1.1(+) R156.1
N62798736: R92.2 U23.8(CS)
N62798740: R93.2 R94.2 U23.7(SA0)
N62798770: C152.1 U23.2(BYP)
N63140042: R6.2 U4.H8(ZQ)
N63140089: R7.2 U5.H8(ZQ)
N63214304: C192.2 C208.2 U39.K2(VDDI)
N63413913: C393.2 U13.26(NC11)
N63414135: C394.2 R311.2 U13.28(NC13)
N63723892: R90.2 U22.11(PS)
N63732974: C193.2 R144.2
N63732975: C194.2 R145.2
N63732976: C195.2 R146.2

Not connected (* = marked no-connect by the designer): J3 3* 4*; J7 3* 4*; U4 A3(NC1)* A7(NF/~{TDQS})* F1(NC2)* F9(NC3)* H1(NC4)* H9(NC5)*; U5 A3(NC1)* A7(NF/~{TDQS})* F1(NC2)* F9(NC3)* H1(NC4)* H9(NC5)*; U13 3(NC3)* 11(NC4)* 20(NC5)* 21(NC6)* 22(NC7)*; U14 3(NC3)* 4(RB4#)* 5(RB3#)* 11(NC4)* 14(CE3#)* 15(CE4#)* 20(NC5)* 21(NC6)* 22(NC7)* 26(NC11)* 27(NC12)* 28(NC13)* 33(NC14)* 40(NC18)* 45(NC19)* 46(NC20)* 47(NC21)*; U15 A2(N/U4)* A8(N/U6)* B5(RE)* C4(N/U8)* C6(N/U7)* D3(N/U22)* D5(N/U23)* D7(N/U24)* E2(N/U20)* E8(N/U5)* F5(~{DQS})* G2(N/U11)* G6(N/U21)* G8(N/U18)* J2(N/U12)* J8(N/U17)* K5(N/U10)* L2(N/U13)* L8(N/U16)* M5(N/U9)* N4(N/U14)* N6(N/U15)* OA1(N/U1)* OA9(N/U3)* OC1(N/U19)* OC9(VREF)* OE1(N/U2)* OE9(VPP)*; U16 A2(N/U4)* A8(N/U6)* B5(RE)* C4(N/U8)* C6(N/U7)* D3(N/U22)* D5(N/U23)* D7(N/U24)* E2(N/U20)* E8(N/U5)* F5(~{DQS})* G2(N/U11)* G6(N/U21)* G8(N/U18)* J2(N/U12)* J8(N/U17)* K5(N/U10)* L2(N/U13)* L8(N/U16)* M5(N/U9)* N4(N/U14)* N6(N/U15)* OA1(N/U1)* OA9(N/U3)* OC1(N/U19)* OC9(VREF)* OE1(N/U2)* OE9(VPP)*; U22 1(SDO)* 5(INT1)* 6(INT2)* 10(CSB)*; U23 3(NC)* 9(INT2)* 11(INT1)* 13(NC1)* 15(NC2)* 16(NC3)*; U24 2(NC1)* 5(~{INT})* 10(NC2)* 11(NC3)* 12(NC4)*; U39 J3(DAT4)* J4(DAT5)* J5(DAT6)* J6(DAT7)*

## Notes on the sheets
sheet 12
- NAND Flash
- (1) 接1片单片选Nand 时，电阻A，B全断开
  (2) 接1片双片选Nand 时，连接电阻A， 断开电阻B
  (3) 接1片四片选Nand 时，连接电阻B， 断开电阻A
  (4) 接2片单片选或接2片双片选Nand 时，连接电阻A， 断开电阻B
- TSOP-48 Nand
- A
- 如果使用tSD，请贴R290 R292 R294 R296 R298 R312
- 如果使用NAND，请贴R299 R313
- 使用tSD（采用SDIO的flash）代替NAND
  FLASH时可以采用此连接，也可以采用
  tSD和NAND FLASH双Layout。
- B
- 第一片nand
- 第二片nand
- tSD电源，如果使用tSD，这部分保留。
- eMMC FLASH
- LGA-60 Nand
- 第一片nand
- 第二片nand
sheet 13
- CARD-DEBUG-GS
- CARD0
- For Boot/Storage
- G-SENSOR
- G-SENSOR IC与屏平行放
  置，放在屏的左上方，
  右上方放置PIN1脚。
- BMA250
- DEBUG
- Option
- MMA8452Q/LIS3DH
- MMA7660FC
- 预留JTAG、UART测试点，
  并要保证测试点方便焊接
  排列整齐，以备调试使用。
- FOR LIS3DH
sheet 14
- BESIDE CPU
- DRAM
- PLL
- Crystal
- CORE
- Layout时晶振下方不可以走线。
- AUDIO&SYS&TP
- PIO-INTFACE
- 此电容必须是105
- CPU&TV
- LAYOUT：按照一个PIN，放一个电容，并且尽量靠近PIN摆放。
- USB
- TWI-PULLUP
- HDMI
- 电容要靠近主控管脚！
sheet 15
- HP-MIC-SPK
- Head Phone
- 该电阻必须保留，
  靠近耳机插座摆放。
- Speaker
- Microphone
sheet 16
- PIO ASSIGNMENT
- Pin
  Group
- Pin
  Group
- Pin
  Group
- Pin
  Group
- Pin
  Group
- Pin Name
- Define
- Function
- Pin Name
- Define
- Function
- Pin Name
- Define
- Function
- Pin Name
- Define
- Function
- Pin Name
- Define
- Function
- PA0
- GPIO
- PC0
- NWE#
- PD18
- LCD0_D18
- PH0
- EINT0
- USB-ICTRL
- PI15
- GPIO
- GPIO
- PC1
- PD19
- LCD0_D19
- PH1
- GPIO_IN
- PI16
- GPIO
- PA1
- NALE
- SD0-DET
- PA2
- GPIO
- PC2
- NCLE
- PD20
- LCD0_D20
- PH2
- GPIO_IN
- PI17
- GPIO
- PI(22)
- PA3
- GPIO
- PC3
- NCE1
- PD21
- LCD0_D21
- PH3
- GPIO_OUT
- USB2-DRV
- PI18
- GPIO
- PC4
- PD22
- LCD0_D22
- PH4
- GPIO_IN
- GPIO
- PA4
- ETXD3
- NCE0
- PD(28)
- LCD
- USB0-IDDET
- PI19
- PA5
- SPI3-CS0
- LCD-CSX
- PC5
- NRE#
- PD23
- LCD0_D23
- PH5
- GPIO_IN
- PI20
- GPIO_OUT
- BT-WAKE
- ACIN-EN
- PA6
- SPI3-CLK
- LCD-SCK
- PC6
- NRB0
- PD24
- LCD0_CLK
- PH6
- GPIO_OUT
- LCD-RST
- PI21
- GPIO_OUT
- BT-HOST-WAKE
- SPI3-MOSI
- LCD-SDI
- PC7
- PD25
- LCD0_DE
- GPIO_OUT
- PA(18)
- PA7
- NRB1
- PH7
- LCD-BL-EN
- SPI3-MISO
- LCD-SDO
- PC8
- NDQ0
- PD26
- LCD0_HSYNC
- PH8
- GPIO_OUT
- PA8
- LCD-PWR
- PA9
- GPIO
- PC9
- NDQ1
- PD27
- LCD0_VSYNC
- PH9
- GPIO_OUT
- WIFI-SHDN
- PA10
- GPIO
- PC10
- NDQ2
- PE0
- CSI0_PCLK
- PH10
- GPIO_IN
- WIFI-HOST-WAKE
- GPIO
- PC11
- NDQ3
- PE1
- CSI0_MCLK
- LCD-SHUT
- PA11
- PH11
- GPIO
- PA12
- GPIO
- PC12
- NDQ4
- PE2
- CSI0_HSYNC
- PH12
- GPIO
- PC(25)
- NAND
- PH(28)
- PA13
- GPIO
- PC13
- NDQ5
- PE3
- CSI0_VSYNC
- PH13
- GPIO_OUT
- CAM-R-RESET#
- GPIO
- PC14
- PE4
- CSI0_D0
- PH14
- GPIO_OUT
- PA14
- NDQ6
- CAM-F-RESET#
- PA15
- GPIO
- PC15
- NDQ7
- PE(12)
- PE5
- CSI0_D1
- CSI0
- PH15
- GPIO_OUT
- PA-SHDN#
- PA16
- GPIO
- PC16
- NWP
- PE6
- CSI0_D2
- PH16
- GPIO_OUT
- CAM-PWR-EN
- 19
- GPIO0
- GPIO
- GPIO
- 18
- USB-WAKEUP
- PA17
- PC17
- NCE2
- PE7
- CSI0_D3
- PH17
- GPIO0
- PC18
- NCE3
- PE8
- CSI0_D4
- PH18
- EINT18
- PMU
- 5
- GPIO0
- NMI#
- PB0
- TWI0_SCK
- PMU
- CAM-R-STBY-EN
- GPIO
- PB1
- TWI0_SDA
- PC19
- GPIO
- PE9
- CSI0_D5
- PH19
- EINT19
- CAM-F-STBY-EN
- 3
- GPIO0
- ACIN-WAKEUP
- CSI0_D6
- PB2
- PWM0
- PWM
- PC20
- GPIO
- PE10
- PH20
- EINT20
- PC21
- GPIO
- PE11
- CSI0_D7
- PH21
- EINT21
- PB3
- GPIO_OUT
- MT-C
- TP-INT
- PB4
- IR0_RX
- IR
- PC22
- GPIO
- PF0
- SDC0_D1
- PH22
- GPIO
- PB5
- GPIO_OUT
- BT-RST
- PC23
- GPIO
- PF1
- SDC0_D0
- PH23
- GPIO
- PC24
- NDQS
- PF2
- SDC0_CLK
- PH24
- GPIO
- PB6
- I2S_BCLK
- BT-PCM-CLK
- PB7
- I2S_LRCK
- BT-PCM-SYNC
- PD0
- LCD0_D0
- PF(6)
- PF3
- SDC0_CMD
- SDC0
- PH25
- GPIO
- PB8
- I2S_DO0
- BT-PCM-OUT
- PD1
- LCD0_D1
- PF4
- SDC0_D3
- PH26
- GPIO
- LCD0_D2
- GPIO
- PB9
- GPIO_OUT
- USB0-DRV
- PD2
- PF5
- SDC0_D2
- PH27
- GPIO
- PD3
- LCD0_D3
- PG0
- CSI1_PCLK
- PI0
- GPIO
- PB10
- PB(24)
- PB11
- GPIO
- PD4
- LCD0_D4
- PG1
- CSI1_MLCK
- PI1
- GPIO
- BT-PCM-IN
- LCD0_D5
- CSI1_HSYNC
- GPIO
- PB12
- I2S_DI
- PD5
- PG2
- PI2
- TP-WAKEUP
- PD6
- LCD0_D6
- PG3
- CSI1_VSYNC
- PI3
- GPIO
- PB13
- GPIO_OUT
- PB14
- JTAG_MS0
- PD7
- LCD0_D7
- PG4
- CSI1_D0
- PI4
- SDC3_CMD
- PD(28)
- LCD
- SDC3_CLK
- PB15
- JTAG_CK0
- JTAG
- PD8
- LCD0_D8
- PG5
- CSI1_D1
- PI5
- PD9
- LCD0_D9
- PG(12)
- PG6
- CSI1_D2
- CSI1
- PI(22)
- PI6
- SDC3_D0
- PB16
- JTAG_DO0
- WIFI
- PB17
- JTAG_DI0
- PD10
- LCD0_D10
- PI7
- SDC3_D1
- PG7
- CSI1_D3
- SDC3_D2
- PB18
- TWI1_SCK
- TWI1
- PD11
- LCD0_D11
- PI8
- PD12
- LCD0_D12
- PI9
- SDC3_D3
- PB19
- TWI1_SDA
- PG8
- CSI1_D4
- PB20
- TWI2_SCK
- PD13
- LCD0_D13
- PI10
- GPIO
- TWI2
- PG9
- CSI1_D5
- PB21
- TWI2_SDA
- PD14
- LCD0_D14
- PI11
- GPIO
- LCD0_D15
- PI12
- SPI0_MOSI
- CLK-32K
- PB22
- UART0_TX
- UART
  (DBUG)
- PD15
- PG10
- CSI1_D6
- PD16
- LCD0_D16
- PI13
- GPIO
- PB23
- UART0_RX
- PG11
- CSI1_D7
- PD17
- LCD0_D17
- PI14
- GPIO
sheet 17
- DDR3-8BITX4
- Please directly copy the refered DRAM layout and follow the PCB
  layout guide. This circuit is only for single-side PCB layout.
sheet 18
- KEY-IR-TVOUT-MT
- TVOUT
- Motor
- 振动马达
- IR MODULE
- KEY
- VOL+
- VOL-
- MENU
- SEARCH
- HOME
- ESC
- ENTER
- VOL+ 0.19V
- VOL- 0.39V
- MENU 0.6V
- SEARCH 0.80V
- HOME 0.98V
- ESC 1.18V
- ENTER 1.4V
- 按键可删除，但名称不能修改，电阻不可删除。
sheet 19
- DDR3-16BITX2
